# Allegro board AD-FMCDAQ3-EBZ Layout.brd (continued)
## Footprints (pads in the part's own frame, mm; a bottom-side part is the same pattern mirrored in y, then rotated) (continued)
QFN24_4X4_2PAD
  oval 0.305x0.889 smd: 1(-1.25,-2.05) 2(-0.75,-2.05) 3(-0.25,-2.05) 4(0.25,-2.05) 5(0.75,-2.05) 6(1.25,-2.05) 13(1.25,2.05) 14(0.75,2.05) 15(0.25,2.05) 16(-0.25,2.05) 17(-0.75,2.05) 18(-1.25,2.05)
  oval 0.889x0.305 smd: 7(2.05,-1.25) 8(2.05,-0.75) 9(2.05,-0.25) 10(2.05,0.25) 11(2.05,0.75) 12(2.05,1.25) 19(-2.05,1.25) 20(-2.05,0.75) 21(-2.05,0.25) 22(-2.05,-0.25) 23(-2.05,-0.75) 24(-2.05,-1.25)
  rect 1.397x2.692 smd: PAD1(-0.648,0)
  rect 0.94x2.692 smd: PAD2(0.876,0)
QFN56_8X8_PAD6_6X6_6
  oval 0.305x0.838 smd: 1(-3.25,-3.95) 2(-2.75,-3.95) 3(-2.25,-3.95) 4(-1.75,-3.95) 5(-1.25,-3.95) 6(-0.75,-3.95) 7(-0.25,-3.95) 8(0.25,-3.95) 9(0.75,-3.95) 10(1.25,-3.95) 11(1.75,-3.95) 12(2.25,-3.95) 13(2.75,-3.95) 14(3.25,-3.95) 29(3.25,3.95) 30(2.75,3.95) 31(2.25,3.95) 32(1.75,3.95) 33(1.25,3.95) 34(0.75,3.95) 35(0.25,3.95) 36(-0.25,3.95) 37(-0.75,3.95) 38(-1.25,3.95) 39(-1.75,3.95) 40(-2.25,3.95) 41(-2.75,3.95) 42(-3.25,3.95)
  oval 0.838x0.305 smd: 15(3.95,-3.25) 16(3.95,-2.75) 17(3.95,-2.25) 18(3.95,-1.75) 19(3.95,-1.25) 20(3.95,-0.75) 21(3.95,-0.25) 22(3.95,0.25) 23(3.95,0.75) 24(3.95,1.25) 25(3.95,1.75) 26(3.95,2.25) 27(3.95,2.75) 28(3.95,3.25) 43(-3.95,3.25) 44(-3.95,2.75) 45(-3.95,2.25) 46(-3.95,1.75) 47(-3.95,1.25) 48(-3.95,0.75) 49(-3.95,0.25) 50(-3.95,-0.25) 51(-3.95,-0.75) 52(-3.95,-1.25) 53(-3.95,-1.75) 54(-3.95,-2.25) 55(-3.95,-2.75) 56(-3.95,-3.25)
  rect 6.604x6.604 smd: PAD(0,0)
QFN64_9X9_PAD7_6X7_6
  oval 0.305x0.838 smd: 1(-3.75,-4.519) 2(-3.25,-4.519) 3(-2.75,-4.519) 4(-2.25,-4.519) 5(-1.75,-4.519) 6(-1.25,-4.519) 7(-0.75,-4.519) 8(-0.25,-4.519) 9(0.25,-4.519) 10(0.75,-4.519) 11(1.25,-4.519) 12(1.75,-4.519) 13(2.25,-4.519) 14(2.75,-4.519) 15(3.25,-4.519) 16(3.75,-4.519) 33(3.75,4.519) 34(3.25,4.519) 35(2.75,4.519) 36(2.25,4.519) 37(1.75,4.519) 38(1.25,4.519) 39(0.75,4.519) 40(0.25,4.519) 41(-0.25,4.519) 42(-0.75,4.519) 43(-1.25,4.519) 44(-1.75,4.519) 45(-2.25,4.519) 46(-2.75,4.519) 47(-3.25,4.519) 48(-3.75,4.519)
  oval 0.838x0.305 smd: 17(4.519,-3.75) 18(4.519,-3.25) 19(4.519,-2.75) 20(4.519,-2.25) 21(4.519,-1.75) 22(4.519,-1.25) 23(4.519,-0.75) 24(4.519,-0.25) 25(4.519,0.25) 26(4.519,0.75) 27(4.519,1.25) 28(4.519,1.75) 29(4.519,2.25) 30(4.519,2.75) 31(4.519,3.25) 32(4.519,3.75) 49(-4.519,3.75) 50(-4.519,3.25) 51(-4.519,2.75) 52(-4.519,2.25) 53(-4.519,1.75) 54(-4.519,1.25) 55(-4.519,0.75) 56(-4.519,0.25) 57(-4.519,-0.25) 58(-4.519,-0.75) 59(-4.519,-1.25) 60(-4.519,-1.75) 61(-4.519,-2.25) 62(-4.519,-2.75) 63(-4.519,-3.25) 64(-4.519,-3.75)
  rect 7.595x7.595 smd: PAD(0,0)
QFN72_10X10_PAD5_3X5_3
  oval 0.305x0.838 smd: 1(-4.25,-4.95) 2(-3.75,-4.95) 3(-3.25,-4.95) 4(-2.75,-4.95) 5(-2.25,-4.95) 6(-1.75,-4.95) 7(-1.25,-4.95) 8(-0.75,-4.95) 9(-0.25,-4.95) 10(0.25,-4.95) 11(0.75,-4.95) 12(1.25,-4.95) 13(1.75,-4.95) 14(2.25,-4.95) 15(2.75,-4.95) 16(3.25,-4.95) 17(3.75,-4.95) 18(4.25,-4.95) 37(4.25,4.95) 38(3.75,4.95) 39(3.25,4.95) 40(2.75,4.95) 41(2.25,4.95) 42(1.75,4.95) 43(1.25,4.95) 44(0.75,4.95) 45(0.25,4.95) 46(-0.25,4.95) 47(-0.75,4.95) 48(-1.25,4.95) 49(-1.75,4.95) 50(-2.25,4.95) 51(-2.75,4.95) 52(-3.25,4.95) 53(-3.75,4.95) 54(-4.25,4.95)
  oval 0.838x0.305 smd: 19(4.95,-4.25) 20(4.95,-3.75) 21(4.95,-3.25) 22(4.95,-2.75) 23(4.95,-2.25) 24(4.95,-1.75) 25(4.95,-1.25) 26(4.95,-0.75) 27(4.95,-0.25) 28(4.95,0.25) 29(4.95,0.75) 30(4.95,1.25) 31(4.95,1.75) 32(4.95,2.25) 33(4.95,2.75) 34(4.95,3.25) 35(4.95,3.75) 36(4.95,4.25) 55(-4.95,4.25) 56(-4.95,3.75) 57(-4.95,3.25) 58(-4.95,2.75) 59(-4.95,2.25) 60(-4.95,1.75) 61(-4.95,1.25) 62(-4.95,0.75) 63(-4.95,0.25) 64(-4.95,-0.25) 65(-4.95,-0.75) 66(-4.95,-1.25) 67(-4.95,-1.75) 68(-4.95,-2.25) 69(-4.95,-2.75) 70(-4.95,-3.25) 71(-4.95,-3.75) 72(-4.95,-4.25)
  rect 5.309x5.309 smd: PAD(0,0)
R0201
  rect 0.356x0.356 smd: 1(-0.318,0) 2(0.318,0)
R0402
  rect 0.889x0.813 smd: 1(-0.635,0) 2(0.635,0)
R0603
  rect 1.092x1.194 smd: 1(-0.851,0) 2(0.851,0)
R0805
  rect 1.295x1.397 smd: 1(-0.953,0) 2(0.953,0)
R1206
  rect 1.6x1.6 smd: 1(-1.397,0) 2(1.397,0)
SC70
  rect 0.406x0.508 smd: 1(-0.65,-0.95) 2(0,-0.95) 3(0.65,-0.95) 4(0.65,0.95) 5(0,0.95) 6(-0.65,0.95)
SO8
  rect 0.61x2.184 smd: 1(-1.905,-2.54) 2(-0.635,-2.54) 3(0.635,-2.54) 4(1.905,-2.54) 5(1.905,2.54) 6(0.635,2.54) 7(-0.635,2.54) 8(-1.905,2.54)
SO8NB-PAD3_1X2_41
  rect 0.635x1.524 smd: 1(-1.905,-2.667) 2(-0.635,-2.667) 3(0.635,-2.667) 4(1.905,-2.667) 5(1.905,2.667) 6(0.635,2.667) 7(-0.635,2.667) 8(-1.905,2.667)
  rect 3.099x2.413 smd: PAD(0,0)
TPSMC30
  round 0.762 smd: 1(0,0)
TSOT-5
  rect 0.508x1.524 smd: 1(-0.95,-1.17) 2(0,-1.17) 3(0.95,-1.17) 4(0.95,1.17) 5(-0.95,1.17)
unnamed#2
  round 1.016 smd: (0,0)
YSML276W197H63
  rect 1.956x1.778 smd: 1(-2.54,-1.83) 2(0,-1.83) 3(2.54,-1.83) 4(2.54,1.83) 5(0,1.83) 6(-2.54,1.83)

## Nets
AGND_SYSREF: C154.2(N2) R31.1 R68.1 U100.56 U100.60
GND: C2.2(N2) C4.1 C5.1 C5.3 C5.5 C5.7 C6.1 C7.1 C7.3 C7.5 C7.7 C9.1 C9.3 C9.5 C9.7 C10.1 C10.3 C10.5 C10.7 C12.1 C12.3 C12.5 C12.7 C13.2(N2) C18.2(N2) C22.1 C23.2(N2) C24.2(N2) C25.2(N2) C26.1 C27.2(N2) C28.2(N2) C29.1 C30.1 C31.N(N2) C32.1 C33.1 C34.2(N2) C35.1 C36.1 C37.1 C38.1 C39.2(N2) C43.1 C45.2(N2) C46.1 C47.1 C48.2(N2) C49.1 C50.1 C51.1 C52.1 C53.1 C54.1 C55.1 C56.1 C57.1 C58.1 C59.1 C60.1 C61.2(N2) C63.1 C64.1 C65.1 C66.1 C67.2(N2) C68.N(N2) C69.2(N2) C70.1 C71.1 C72.1 C73.1 C76.N(N2) C77.1 C78.1 C79.1 C80.1 C81.1 C82.1 C83.1 C89.2(N2) C90.1 C91.2(N2) C94.1 C96.N(N2) C97.1 C98.1 C100.2(N2) C101.1 C103.2(N2) C104.1 C105.1 C106.2(N2) C107.1 C109.1 C112.2(N2) C113.1 C114.1 C115.1 C116.2(N2) C117.1 C119.2(N2) C120.1 C121.1 C122.1 C123.2(N2) C125.2(N2) C126.2(N2) C127.1 C128.1 C129.2(N2) C130.2(N2) C131.2(N2) C133.2(N2) C134.2(N2) C135.2(N2) C136.2(N2) C137.2(N2) C138.2(N2) C139.2(N2) C140.2(N2) C141.2(N2) C142.2(N2) C143.2(N2) C144.2(N2) C145.2(N2) C146.2(N2) C147.2(N2) C148.2(N2) C149.2(N2) C150.2(N2) C151.2(N2) C152.2(N2) C153.2(N2) C155.2(N2) C156.1 C157.1 C158.1 C159.1 C160.1 C161.1 C163.2(N2) C164.2(N2) C165.2(N2) C166.2(N2) C167.N(N2) C169.1 C170.N(N2) C173.2(N2) C175.2(N2) C176.2(N2) C177.2(N2) C178.2(N2) C179.2(N2) C180.2(N2) C181.2(N2) C182.N(N2) C183.2(N2) C184.2(N2) C186.N(N2) C190.1 C191.1 C192.1 C195.2(N2) C197.2(N2) C199.1 C204.1 C205.1 C206.1 C207.2(N2) C208.2(N2) C209.2(N2) C210.2(N2) C211.2(N2) C212.2(N2) C216.1 C217.1 C218.2(N2) C219.1 C220.2(N2) C222.N(N2) C225.2(N2) C226.2(N2) C227.2(N2) C228.2(N2) C229.2(N2) C230.2(N2) C231.2(N2) C232.2(N2) C233.2(N2) C234.2(N2) C235.2(N2) C236.2(N2) C261.2(N2) C262.2(N2) C535.1 CC0.2(N2) CC02.1 CF1.1 CF2.1 CF3.1 CF4.1 CF5.1 CIN11.1 CIN12.1 CIN21.1 CIN22.1 CN4.1 CN4.3 CN4.5 CN4.7 CO1.1 CO2.1 CO3.1 CO4.1 CO5.1 CO6.1 CO7.1 CO8.1 CR1.C CSS1.1 CSS2.1 CVREG1.1 CVREG2.1 GND.1(N1) J1.2 J1.3 J1.4 J1.5(SH4) JP3.1 P501.A1 P501.A4 P501.A5 P501.A8 P501.A9 P501.A12 P501.A13 P501.A16 P501.A17 P501.A20 P501.A21 P501.A24 P501.A25 P501.A28 P501.A29 P501.A32 P501.A33 P501.A36 P501.A37 P501.A40 P501.B2 P501.B3 P501.B6 P501.B7 P501.B10 P501.B11 P501.B14 P501.B15 P501.B18 P501.B19 P501.B22 P501.B23 P501.B26 P501.B27 P501.B30 P501.B31 P501.B34 P501.B35 P501.B38 P501.B39 P501.C1 P501.C4 P501.C5 P501.C8 P501.C9 P501.C12 P501.C13 P501.C16 P501.C17 P501.C20 P501.C21 P501.C24 P501.C25 P501.C28 P501.C29 P501.C32 P501.C33 P501.C36 P501.C38 P501.C40 P501.D2 P501.D3 P501.D6 P501.D7 P501.D10 P501.D13 P501.D16 P501.D19 P501.D22 P501.D25 P501.D28 P501.D37 P501.D39 P501.E1 P501.E4 P501.E7 P501.E10 P501.E13 P501.E16 P501.E19 P501.E22 P501.E25 P501.E28 P501.E31 P501.E34 P501.E37 P501.E40 P501.F2 P501.F3 P501.F6 P501.F9 P501.F12 P501.F15 P501.F18 P501.F21 P501.F24 P501.F27 P501.F30 P501.F33 P501.F36 P501.F39 P501.G1 P501.G4 P501.G5 P501.G8 P501.G11 P501.G14 P501.G17 P501.G20 P501.G23 P501.G26 P501.G29 P501.G32 P501.G35 P501.G38 P501.G40 P501.H2 P501.H3 P501.H6 P501.H9 P501.H12 P501.H15 P501.H18 P501.H21 P501.H24 P501.H27 P501.H30 P501.H33 P501.H36 P501.H39 P501.J1 P501.J4 P501.J5 P501.J8 P501.J11 P501.J14 P501.J17 P501.J20 P501.J23 P501.J26 P501.J29 P501.J32 P501.J35 P501.J38 P501.J40 P501.K2 P501.K3 P501.K6 P501.K9 P501.K12 P501.K15 P501.K18 P501.K21 P501.K24 P501.K27 P501.K30 P501.K33 P501.K36 P501.K39 R1.2(N2) R7.1 R9.2(N2) R16.1 R17.1 R18.1 R19.1 R20.2(N2) R26.1 R31.2(N2) R33.2(N2) R36.1 R38.2(N2) R39.1 R42.1 R43.1 R44.1 R48.2(N2) R50.1 R52.1 R57.2(N2) R58.2(N2) R60.1 R62.1 R64.1 R65.1 R67.1 R68.2(N2) R69.1 R70.1 R73.1 R79.2(N2) R80.1 R81.1 R85.2(N2) R92.2(N2) R93.1 R100.1 R116.1 R117.1 R120.1 R121.2(N2) R138.2(N2) RC1.1 RC12.1 RF2.1 RT1.2(N2) RT22.1 RX_A.2 RX_A.3 RX_A.4 RX_A.5(SH4) RX_B.2 RX_B.3 RX_B.4 RX_B.5(SH4) T3.3 T4.1 T100.1 T100.4 T101.4 T102.1 T102.4 T103.5(N4) TP1.1(N1) TX_A.2 TX_A.3 TX_A.4 TX_A.5(SH4) TX_B.2 TX_B.3 TX_B.4 TX_B.5(SH4) U1.PAD U2.3 U2.4 U3.4 U3.8 U3.9 U3.10 U3.11 U3.12 U3.13 U3.PAD1 U4.2 U5.6 U5.PAD U6.4 U6.8 U6.9 U6.10 U6.11 U6.12 U6.13 U6.PAD1 U7.9 U7.13 U7.PAD U8.4 U8.PAD U9.2 U10.3 U10.6 U10.PAD U11.3 U11.6 U11.PAD U12.11 U12.12 U12.13 U13.11 U13.12 U13.13 U14.2 U14.4 U15.4 U16.2 U17.6 U17.PAD U18.6 U18.9 U18.PAD U19.6 U19.PAD U22.2 U100.16 U100.18 U100.31 U100.33 U100.PAD Y1.3
P1V7: C167.P C186.P CO5.2(N2) CO6.2(N2) CO7.2(N2) CO8.2(N2) L12.2(N2) R40.2(N2) RFB2.2(N2) TP3.1(N1) U17.1 U17.2 U17.3 U17.4 U17.15 U17.16 U19.1 U19.2 U19.3 U19.4 U19.15 U19.16
P2V5_EN: U4.4(Y2) U5.4
P3V3_CLK_OUT: C24.1 C30.2(N2) C32.2(N2) C59.2(N2) C63.2(N2) C65.2(N2) C66.2(N2) C70.2(N2) C72.2(N2) C77.2(N2) C78.2(N2) C79.2(N2) C80.2(N2) C82.2(N2) C83.2(N2) E11.2(N2) U7.27 U7.30 U7.33 U7.36 U7.39 U7.42 U7.45 U7.48 U7.51 U7.54 U7.60 U7.63 U7.66 U7.69
P3V3_CLK_PLL: C23.1 C60.2(N2) C64.2(N2) C71.2(N2) C73.2(N2) C81.2(N2) E8.2(N2) U7.1 U7.10 U7.16 U7.20 U7.72(VDD_5)
P3V6: C18.1 C34.1 C48.1 C106.1 C112.1 C149.1 C152.1 C163.1 C166.1 C262.1 CO1.2(N2) CO2.2(N2) CO3.2(N2) CO4.2(N2) L11.2(N2) R33.1 R63.2(N2) RFB1.2(N2) TP2.1(N1) U4.3 U8.7 U8.8 U10.5 U10.8 U11.5 U11.8 U16.1 U16.3 U22.1 U22.3
VINA1_N: C187.1 T100.5(N4) T101.1
VINA1_P: C108.1 T100.3 T101.3
VINA_N: C196.1 R109.2(N2) U100.5
VINA_P: C196.2(N2) R108.2(N2) U100.6
VINB1_N: C118.1 T102.3 T103.3
VINB1_P: C188.1 T102.5(N4) T103.1
VINB_N: C198.2(N2) R126.2(N2) U100.44
VINB_P: C198.1 R127.2(N2) U100.43
3P3_SUP: C25.1 C28.1 C68.P C76.P C91.1 C233.1 C234.1 C261.1 R27.2(N2) U9.6(VCCB) U12.23 U12.24(VCCB2) U13.23 U13.24(VCCB2) U14.1(VCC) U15.1(VCC) U22.5(VOUT)
3P3_XO: C119.1 C126.1 C184.1 C535.2(N2) R6.1 U16.5(VOUT) Y1.6(VDD)
ADC_1P0: C100.1 U100.12(V_1P0)
ADC_1P2_AVDD: C135.1 C136.1 C137.1 C138.1 C139.1 C144.1 C145.1 C146.1 C147.1 C225.1 E1.2(N2) U100.1 U100.2 U100.47 U100.48 U100.49 U100.52 U100.55 U100.61 U100.64
ADC_1P2_AVDD_SR: C154.1 C226.1 E2.2(N2) U100.57
ADC_1P2_DRVDD: C155.1 C208.1 C209.1 C210.1 C211.1 C212.1 C232.1 E9.2(N2) U100.19 U100.30
ADC_1P2_DVDD: C153.1 C207.1 C227.1 E3.2(N2) U100.15 U100.34
ADC_2P5_AVDD: C96.P C123.1 C125.1 C129.1 C130.1 C131.1 C133.1 C134.1 C173.1 C175.1 C176.1 C177.1 C179.1 C195.1 E17.2(N2) R61.2(N2) U100.3 U100.8 U100.9 U100.10 U100.11 U100.39 U100.40 U100.41 U100.46 U100.50 U100.51 U100.62 U100.63
ADC_3P3_AVDD: C140.1 C141.1 C142.1 C143.1 C181.1 E20.2(N2) U100.4 U100.7 U100.42 U100.45
ADC_3P3_SPIVDD: C150.1 C151.1 C220.1 E21.2(N2) U100.13 U100.38
ADC_CLK1_N: C40.1 U7.26
ADC_CLK1_P: C41.1 U7.25
ADC_CLK_FMC1_N: C168.1 U7.53
ADC_CLK_FMC1_P: C162.1 U7.52
ADC_CLK_FMC_N: C174.2(N2) P501.B21
ADC_CLK_FMC_P: C171.2(N2) P501.B20
ADC_CLK_N: C40.2(N2) R56.1 U100.54
ADC_CLK_P: C41.2(N2) R56.2(N2) U100.53
ADC_FDA: R77.2(N2) U100.17
ADC_FDB: R78.2(N2) U100.32
ADC_PD: R95.2(N2) U100.14
ADC_REFCLK_N: C193.2(N2) P501.G7
ADC_REFCLK_P: C194.2(N2) P501.G6
ADC_SERDOUT0_N: C20.2(N2) U100.22
ADC_SERDOUT0_P: C8.2(N2) U100.23
ADC_SERDOUT1_N: C85.2(N2) U100.24
ADC_SERDOUT1_P: C84.2(N2) U100.25
ADC_SERDOUT2_N: C87.2(N2) U100.26
ADC_SERDOUT2_P: C86.2(N2) U100.27
ADC_SERDOUT3_N: C92.2(N2) U100.28
ADC_SERDOUT3_P: C88.2(N2) U100.29
ADC_SPI_CSB: ADC_CSB.1(N1) R97.2(N2) U100.37
ADC_SYNC_N: P501.D9 R72.1 U100.20
ADC_SYNC_P: P501.D8 R72.2(N2) U100.21
ADC_SYSREF1_N: C14.1 U7.50
ADC_SYSREF1_P: C19.1 U7.49
ADC_SYSREF_N: C172.2(N2) R55.1 U100.59
ADC_SYSREF_P: C15.2(N2) R55.2(N2) U100.58
CLKD_SPI_CSB: CLKD_CSB.1(N1) R94.2(N2) U7.21
CLKD_STATUS0: R82.2(N2) U7.56
CLKD_STATUS1: R76.2(N2) U7.55
CLKD_SYSREF_ADC1_N: C21.1 U7.47
CLKD_SYSREF_ADC1_P: C17.1 U7.46
CLKD_SYSREF_ADC_N: C11.2(N2) P501.G10
CLKD_SYSREF_ADC_P: C16.2(N2) P501.G9
CLKD_SYSREF_DAC1_N: C11.1 U7.44
CLKD_SYSREF_DAC1_P: C16.1 U7.43
CLKD_SYSREF_DAC_N: C21.2(N2) P501.H11
CLKD_SYSREF_DAC_P: C17.2(N2) P501.H10
DAC_1P2_CVDD12: C9.2 C9.4 C9.6 C9.8(N8) C35.2(N2) C38.2(N2) C90.2(N2) C97.2(N2) C104.2(N2) C113.2(N2) C120.2(N2) C127.2(N2) C231.1 E7.2(N2) U1.2 U1.47 U1.50 U1.56
DAC_1P2_DVDD12: C5.2 C5.4 C5.6 C5.8(N8) C98.2(N2) C114.2(N2) C121.2(N2) C128.2(N2) C229.1 E5.2(N2) U1.11 U1.35 U1.36
DAC_1P2_PVDD12: C7.2 C7.4 C7.6 C7.8(N8) C29.2(N2) C36.2(N2) C49.2(N2) C53.2(N2) C228.1 E4.2(N2) U1.5 U1.21
DAC_1P2_SVDD12: C6.2(N2) C10.2 C10.4 C10.6 C10.8(N8) C12.2 C12.4 C12.6 C12.8(N8) C22.2(N2) C26.2(N2) C33.2(N2) C37.2(N2) C43.2(N2) C47.2(N2) C50.2(N2) C52.2(N2) C54.2(N2) C55.2(N2) C56.2(N2) C94.2(N2) C101.2(N2) C109.2(N2) C117.2(N2) C122.2(N2) C204.2(N2) C205.2(N2) C206.2(N2) C230.1 E6.2(N2) U1.12 U1.13 U1.14 U1.17 U1.20 U1.23 U1.26 U1.29 U1.30(VTT2) U1.31
DAC_3P3_AVDD33: C42.1 C44.1 C46.2(N2) C51.2(N2) C156.2(N2) C157.2(N2) C158.2(N2) C159.2(N2) C160.2(N2) C161.2(N2) C164.1 CN4.2 CN4.4 CN4.6 CN4.8(N8) E10.2(N2) R15.1 R22.2(N2) R23.1 R25.2(N2) U1.43 U1.46 U1.51 U1.54
DAC_3P3_IOVDD33: C57.2(N2) C58.2(N2) C180.1 C191.2(N2) C192.2(N2) E12.2(N2) R122.2(N2) U1.32 U1.42
DAC_CLK1_N: C1.1 U7.62
DAC_CLK1_P: C3.1 U7.61
DAC_CLK_FMC1_N: C174.1 U7.38
DAC_CLK_FMC1_P: C171.1 U7.37
DAC_CLK_FMC_N: C168.2(N2) P501.D5
DAC_CLK_FMC_P: C162.2(N2) P501.D4
DAC_CLK_N: C1.2(N2) R14.2(N2) U1.49
DAC_CLK_P: C3.2(N2) R14.1 U1.48
DAC_IRQ: R84.2(N2) U1.10
DAC_REFCLK_N: C185.2(N2) P501.D21
DAC_REFCLK_P: C189.2(N2) P501.D20
DAC_SERDIN0_N: C95.2(N2) U1.16
DAC_SERDIN0_P: C93.2(N2) U1.15
DAC_SERDIN1_N: C102.2(N2) U1.19
DAC_SERDIN1_P: C99.2(N2) U1.18
DAC_SERDIN2_N: C111.2(N2) U1.24
DAC_SERDIN2_P: C110.2(N2) U1.25
DAC_SERDIN3_N: C132.2(N2) U1.27
DAC_SERDIN3_P: C124.2(N2) U1.28
DAC_SPI_CSB: R98.2(N2) U1.41
DAC_SYNC_N: P501.H8 U1.33
DAC_SYNC_P: P501.H7 U1.34
DAC_SYSREF1_N: C172.1 U7.41
DAC_SYSREF1_P: C15.1 U7.40
DAC_SYSREF_N: C14.2(N2) R13.2(N2) U1.7
DAC_SYSREF_P: C19.2(N2) R13.1 U1.6
DAC_TXEN: R96.2(N2) U1.8
DLOGIC_0: P501.A14 P501.A18 P501.B4 P501.B8 P501.B12 P501.B16 P501.H4 P501.J2 P501.K4 U14.7
DLOGIC_1: P501.A15 P501.A19 P501.B5 P501.B9 P501.B13 P501.B17 P501.H5 P501.J3 P501.K5 U14.8
EXT_TRIG_N: P501.H14 R35.2(N2) U15.8
EXT_TRIG_P: P501.H13 R35.1 U15.7
FMC_3P3V: C31.P C69.1 P501.C39 P501.D36 P501.D38 P501.D40 R32.1 R59.2(N2) U4.5 U5.1 U5.2 U5.3 U5.15 U5.16 UNK3P3V.1
FMC_3P3VAUX: C67.1 C217.2(N2) C218.1 P501.D32 R12.2(N2) R28.1 R29.1 R30.1 U2.8 U18.10 U18.16 U18.17
FMC_12P0V: C237.2(N2) LIN1.1 LIN2.1 P501.C35 P501.C37 R66.2(N2) UNK12P0V.1
FMC_ADC_FDA: P501.H16 R45.1
FMC_ADC_FDB: P501.H17 R71.1
FMC_ADC_PD: P501.C10 R87.1
FMC_ADC_SPI_CSB: P501.D15 R89.1
FMC_CLK_DIR: P501.B1 R19.2(N2)
FMC_CLKD_SPI_CSB: P501.D11 R86.1
FMC_CLKD_STATUS0: P501.G12 R74.1
FMC_CLKD_STATUS1: P501.G13 R41.1
FMC_DAC_IRQ: P501.G15 R75.1
FMC_DAC_SPI_CSB: P501.C14 R90.1
FMC_DAC_TXEN: P501.G16 R88.1
FMC_GA0: P501.C34 R11.1 U18.11
FMC_GA1: P501.D35 R10.1 U18.13
FMC_PG_C2M: P501.D1 U3.20 U6.20
FMC_SCL: P501.C30 R28.2(N2) U2.6 U18.15
FMC_SDA: P501.C31 R30.2(N2) U2.5 U18.14
FMC_SERDIN0_N: C95.1 P501.A31
FMC_SERDIN0_P: C93.1 P501.A30
FMC_SERDIN1_N: C102.1 P501.A27
FMC_SERDIN1_P: C99.1 P501.A26
FMC_SERDIN2_N: C111.1 P501.A23
FMC_SERDIN2_P: C110.1 P501.A22
FMC_SERDIN3_N: C132.1 P501.C3
FMC_SERDIN3_P: C124.1 P501.C2
FMC_SERDOUT0_N: C20.1 P501.A11
FMC_SERDOUT0_P: C8.1 P501.A10
FMC_SERDOUT1_N: C85.1 P501.C7
FMC_SERDOUT1_P: C84.1 P501.C6
FMC_SERDOUT2_N: C87.1 P501.A7
FMC_SERDOUT2_P: C86.1 P501.A6
FMC_SERDOUT3_N: C92.1 P501.A3
FMC_SERDOUT3_P: C88.1 P501.A2
FMC_SPI_SCLK: P501.D12 R91.1
FMC_SPI_SDIO: P501.D14 R115.1
FMC_SPI_SDIO_CTRL: P501.C11 U9.5
FMC_SYSREF_N: P501.D18 R112.1
FMC_SYSREF_N_A: R112.2(N2) R114.2(N2) U7.71
FMC_SYSREF_P: P501.D17 R113.1
FMC_SYSREF_P_A: R113.2(N2) R114.1 U7.70
FMC_VADJ: C89.1 C235.1 C236.1 P501.E39 P501.F40 P501.G39 P501.H40 R8.1 R24.2(N2) R119.2(N2) U9.1 U12.1 U13.1 VADJ.1(N1)
LDO_VCO_2P5: C62.1 C103.1 U7.15
LF_EXT_CAP: C2.1 R2.1 U7.7
LF_PLL2: R83.2(N2) U7.14
OUT0_N: R22.1 T2.1 U1.52
OUT0_P: R15.2(N2) T2.3 U1.53
OUT1_N: R23.2(N2) T1.3 U1.45
OUT1_P: R25.1 T1.1 U1.44
PWRGD: R32.2(N2) U3.21 U4.1 U5.5 U6.21 U10.7 U11.7 U17.5 U19.5
SPI_SCLK: R99.2(N2) R101.1 R104.1 R106.2(N2) SCLK.1(N1)
SPI_SDIO: R4.1 R105.1 R107.2(N2) R118.2(N2) SDIO.1(N1)
SW1: CBST1.2(N2) L1.1 R3.1 U6.5 U6.6 U6.7 U6.14 U6.PAD2
UNNAMED_2_AD9152_I234_I120: R17.2(N2) U1.55
UNNAMED_2_AD9152_I234_LDOBYP1: C199.2(N2) U1.1
UNNAMED_2_AD9152_I234_LDOBYP2: C39.1 U1.22
UNNAMED_2_AD9152_I234_PAPOUT0: R20.1 U1.37
UNNAMED_2_AD9152_I234_REFCLK: R16.2(N2) U1.3
UNNAMED_2_AD9152_I234_REFCLK_1: R18.2(N2) U1.4
UNNAMED_2_AD9152_I234_RESETB: R122.1 U1.9
UNNAMED_2_AD9152_I234_SPICLK: R106.1 U1.40
UNNAMED_2_AD9152_I234_SPISDIO: R107.1 U1.39
UNNAMED_2_CAP_I167_N2: C44.2(N2) T4.5
UNNAMED_2_CAP_I184_N2: C42.2(N2) T3.5
UNNAMED_2_CNBNC5P_I224_CNTR: T4.3 TX_B.1
UNNAMED_2_CNBNC5P_I229_CNTR: T3.1 TX_A.1
UNNAMED_2_XFMRETC1_I243_N3: T2.4 T3.4(SECP)
UNNAMED_2_XFMRETC1_I243_N4: T2.5(N4) T3.6
UNNAMED_2_XFMRETC1_I246_N3: T1.4 T4.4(SECP)
UNNAMED_2_XFMRETC1_I246_N4: T1.5(N4) T4.6
UNNAMED_4_AD9528_I220_OUT3: C189.1 U7.58
UNNAMED_4_AD9528_I220_OUT3N: C185.1 U7.59
UNNAMED_4_AD9528_I220_OUT10: C194.1 U7.34
UNNAMED_4_AD9528_I220_OUT10N: C193.1 U7.35
UNNAMED_4_AD9528_I220_SCLK: R101.2(N2) U7.22
UNNAMED_4_AD9528_I220_SDIO: R4.2(N2) U7.23
UNNAMED_4_CAP_I87_N1: C75.1 R58.1 Y1.5
UNNAMED_4_CAP_I87_N2: C75.2(N2) R5.2(N2) U7.12
UNNAMED_4_CAP_I90_N1: C74.1 R48.1 Y1.4
UNNAMED_4_CAP_I90_N2: C74.2(N2) R5.1 U7.11
UNNAMED_4_CAP_I173_N1: C61.1 R2.2(N2)
UNNAMED_4_CAP_I217_N2: C62.2(N2) R83.1
UNNAMED_4_RES_I223_N2: R1.1 R6.2(N2) Y1.1
UNNAMED_5_AD9680_I130_SCLK: R104.2(N2) U100.36
UNNAMED_5_AD9680_I130_SDIO: R105.2(N2) U100.35
UNNAMED_5_CAP_I52_N2: C108.2(N2) R103.1
UNNAMED_5_CAP_I53_N2: C187.2(N2) R102.1
UNNAMED_5_CAP_I54_N2: C107.2(N2) R110.2(N2) R111.1
UNNAMED_5_CAP_I67_N2: C190.2(N2) R128.2(N2) R129.1
UNNAMED_5_CAP_I68_N2: C188.2(N2) R54.1
UNNAMED_5_CAP_I69_N2: C118.2(N2) R53.1
UNNAMED_5_CAP_I181_N2: C105.2(N2) R103.2(N2) R108.1 R110.1
UNNAMED_5_CAP_I182_N1: C197.1 R102.2(N2) R109.1 R111.2(N2)
UNNAMED_5_CAP_I183_N2: C115.2(N2) R53.2(N2) R126.1 R128.1
UNNAMED_5_CAP_I184_N1: C116.1 R54.2(N2) R127.1 R129.2(N2)
UNNAMED_5_CNBNC5P_I49_CNTR: R121.1 RX_A.1 T101.5(N4)
UNNAMED_5_CNBNC5P_I70_CNTR: R138.1 RX_B.1 T103.4
UNNAMED_6_CN400PAKV2_I20_TDI: P501.D30 P501.D31
UNNAMED_7_AD7291_I66_DCAP: C216.2(N2) U18.8
UNNAMED_7_AD7291_I66_VIN5: R66.1 R67.2(N2) U18.3
UNNAMED_7_AD7291_I66_VIN6: R24.1 R26.2(N2) U18.4
UNNAMED_7_AD7291_I66_VIN7: R27.1 R36.2(N2) U18.5
UNNAMED_7_AD7291_I66_VREF: C219.2(N2) U18.7(VREF)
UNNAMED_7_ADN4661_I56_DIN: J1.1 R9.1 U15.2
UNNAMED_7_DIOLED_I43_P: CR1.A(P) R34.2(N2)
UNNAMED_7_ICFXL4245_I164_A0: R74.2(N2) U13.3
UNNAMED_7_ICFXL4245_I164_A1: R41.2(N2) U13.4
UNNAMED_7_ICFXL4245_I164_A2: R75.2(N2) U13.5
UNNAMED_7_ICFXL4245_I164_A3: R45.2(N2) U13.6
UNNAMED_7_ICFXL4245_I164_A4: R71.2(N2) U13.7
UNNAMED_7_ICFXL4245_I164_A5: R65.2(N2) U13.8
UNNAMED_7_ICFXL4245_I164_A6: R73.2(N2) U13.9
UNNAMED_7_ICFXL4245_I164_A7: R70.2(N2) U13.10
UNNAMED_7_ICFXL4245_I164_B0: R82.1 U13.21
UNNAMED_7_ICFXL4245_I164_B1: R76.1 U13.20
UNNAMED_7_ICFXL4245_I164_B2: R84.1 U13.19
UNNAMED_7_ICFXL4245_I164_B3: R77.1 U13.18
UNNAMED_7_ICFXL4245_I164_B4: R78.1 U13.17
UNNAMED_7_ICFXL4245_I164_B5: R116.2(N2) U13.16
UNNAMED_7_ICFXL4245_I164_B6: R81.2(N2) U13.15
UNNAMED_7_ICFXL4245_I164_B7: R117.2(N2) U13.14
UNNAMED_7_ICFXL4245_I164_OEN: R80.2(N2) U13.22
UNNAMED_7_ICFXL4245_I164_TRN: R79.1 U13.2
UNNAMED_7_ICFXL4245_I213_A0: R91.2(N2) U12.3
UNNAMED_7_ICFXL4245_I213_A1: R85.1 U12.4
UNNAMED_7_ICFXL4245_I213_A2: R92.1 U12.5
UNNAMED_7_ICFXL4245_I213_A3: R86.2(N2) U12.6
UNNAMED_7_ICFXL4245_I213_A4: R89.2(N2) U12.7
UNNAMED_7_ICFXL4245_I213_A5: R87.2(N2) U12.8
UNNAMED_7_ICFXL4245_I213_A6: R90.2(N2) U12.9
UNNAMED_7_ICFXL4245_I213_A7: R88.2(N2) U12.10
UNNAMED_7_ICFXL4245_I213_B0: R99.1 U12.21
UNNAMED_7_ICFXL4245_I213_B1: R100.2(N2) U12.20
UNNAMED_7_ICFXL4245_I213_B2: R93.2(N2) U12.19
UNNAMED_7_ICFXL4245_I213_B3: R94.1 U12.18
UNNAMED_7_ICFXL4245_I213_B4: R97.1 U12.17
UNNAMED_7_ICFXL4245_I213_B5: R95.1 U12.16
UNNAMED_7_ICFXL4245_I213_B6: R98.1 U12.15
UNNAMED_7_ICFXL4245_I213_B7: R96.1 U12.14
UNNAMED_7_ICFXL4245_I213_OEN: R120.2(N2) U12.22
UNNAMED_7_ICFXL4245_I213_TRN: R119.1 U12.2
UNNAMED_7_ICFXLH1T45_I232_A: R115.2(N2) U9.3
UNNAMED_7_ICFXLH1T45_I232_B: R118.1 U9.4
UNNAMED_7_ICM24CXX_I21_E0: R10.2(N2) U2.1
UNNAMED_7_ICM24CXX_I21_E1: R11.2(N2) U2.2
UNNAMED_7_ICM24CXX_I21_WCN: JP3.2(N2) R29.2(N2) U2.7(WC_N)
UNNAMED_7_NC7WZ17P6X_I12_Y1: R34.1 U4.6
UNNAMED_7_RES_I67_N1: R12.1 R39.2(N2) U18.20
UNNAMED_7_RES_I85_N1: R59.1 R60.2(N2) U18.19
UNNAMED_7_RES_I87_N2: R63.1 R64.2(N2) U18.18
UNNAMED_7_RES_I91_N1: R61.1 R62.2(N2) U18.2
UNNAMED_7_RES_I93_N1: R40.1 R42.2(N2) U18.1
UNNAMED_8_ADM7154_I184_BYP: C165.1 U8.3
UNNAMED_8_ADM7154_I184_REF: C183.1 U8.5 U8.6
UNNAMED_8_ADM7154_I184_VREG: C178.1 U8.1(VREG)
UNNAMED_8_ADP238X_I102_BST: CBST1.1 U6.15
UNNAMED_8_ADP238X_I102_COMP: CC0.1 CC1.1 U6.1
UNNAMED_8_ADP238X_I102_RT: RT1.1 U6.22
UNNAMED_8_ADP238X_I102_SS: CSS1.2(N2) U6.24
UNNAMED_8_ADP238X_I102_VREG: CVREG1.2(N2) U6.3(VREG)
UNNAMED_8_ADP1755_I190_ADJ: R37.2(N2) R38.1 U5.9
UNNAMED_8_ADP1755_I190_SS: C148.1 U5.7
UNNAMED_8_ADP1755_I190_VOUT1: C182.P E17.1 R37.1 U5.10 U5.11 U5.12 U5.13 U5.14(VOUT5)
UNNAMED_8_ADP7104_I66_SENSE: R44.2(N2) R47.1 U11.2
UNNAMED_8_ADP7104_I66_VOUT: C45.1 E20.1 E21.1 R47.2(N2) U11.1(VOUT)
UNNAMED_8_ADP7104_I68_SENSE: R43.2(N2) R46.1 U10.2
UNNAMED_8_ADP7104_I68_VOUT: C13.1 E10.1 E12.1 R46.2(N2) U10.1(VOUT)
UNNAMED_8_CAP_I10_N2: CC1.2(N2) RC1.2(N2)
UNNAMED_8_CAP_I92_N1: C27.1 E8.1 E11.1 U8.2
UNNAMED_8_CAP_I104_N1: CF1.2(N2) CF2.2(N2) CF3.2(N2) CFB1.1 L1.2(N2) L11.1
UNNAMED_8_CAP_I104_N2: CFB1.2(N2) RF1.2(N2) RFB1.1
UNNAMED_8_CAP_I171_N2: CIN11.2(N2) CIN21.2(N2) LIN1.2(N2) U6.16 U6.17 U6.18 U6.19
UNNAMED_8_CAP_I177_N1: C237.1 R69.2(N2)
UNNAMED_8_RES_I185_N2: RF1.1 RF2.2(N2) U6.2
UNNAMED_9_ADP238X_I75_BST: CBST2.1 U3.15
UNNAMED_9_ADP238X_I75_COMP: CC02.2(N2) CC12.2(N2) U3.1
UNNAMED_9_ADP238X_I75_RT: RT22.2(N2) U3.22
UNNAMED_9_ADP238X_I75_SS: CSS2.2(N2) U3.24
UNNAMED_9_ADP238X_I75_SW1: CBST2.2(N2) L10.1 U3.5 U3.6 U3.7 U3.14 U3.PAD2
UNNAMED_9_ADP238X_I75_VREG: CVREG2.2(N2) U3.3(VREG)
UNNAMED_9_ADP1741_I185_ADJ: R49.1 R50.2(N2) U17.9
UNNAMED_9_ADP1741_I185_SS: C169.2(N2) U17.7
UNNAMED_9_ADP1741_I185_VOUT: C170.P E1.1 E2.1 E3.1 E9.1 R49.2(N2) U17.10 U17.11 U17.12 U17.13 U17.14(VOUT4)
UNNAMED_9_ADP1741_I188_ADJ: R51.1 R52.2(N2) U19.9
UNNAMED_9_ADP1741_I188_SS: C4.2(N2) U19.7
UNNAMED_9_ADP1741_I188_VOUT: C222.P E4.1 E5.1 E6.1 E7.1 R51.2(N2) U19.10 U19.11 U19.12 U19.13 U19.14(VOUT4)
UNNAMED_9_CAP_I146_N1: CC12.1 RC12.2(N2)
UNNAMED_9_CAP_I148_N1: CFB2.1 R21.2(N2) RFB2.1
UNNAMED_9_CAP_I148_N2: CF4.2(N2) CF5.2(N2) CFB2.2(N2) L10.2(N2) L12.1
UNNAMED_9_CAP_I180_N2: CIN12.2(N2) CIN22.2(N2) LIN2.2(N2) U3.16 U3.17 U3.18 U3.19
UNNAMED_9_RES_I163_N1: R3.2(N2) R57.1 U3.23
UNNAMED_9_RES_I176_N1: R7.2(N2) R21.1 U3.2
VIO_B_M2C: P501.J39 P501.K40 R8.2(N2)

Pads without a net: P501 A34 A35 A38 A39 B24 B25 B28 B29 B32 B33 B36 B37 B40 C15 C18 C19 C22 C23 C26 C27 D23 D24 D26 D27 D29 D33 D34 E2 E3 E5 E6 E8 E9 E11 E12 E14 E15 E17 E18 E20 E21 E23 E24 E26 E27 E29 E30 E32 E33 E35 E36 E38 F1 F4 F5 F7 F8 F10 F11 F13 F14 F16 F17 F19 F20 F22 F23 F25 F26 F28 F29 F31 F32 F34 F35 F37 F38 G2 G3 G18 G19 G21 G22 G24 G25 G27 G28 G30 G31 G33 G34 G36 G37 H1 H19 H20 H22 H23 H25 H26 H28 H29 H31 H32 H34 H35 H37 H38 J6 J7 J9 J10 J12 J13 J15 J16 J18 J19 J21 J22 J24 J25 J27 J28 J30 J31 J33 J34 J36 J37 K1 K7 K8 K10 K11 K13 K14 K16 K17 K19 K20 K22 K23 K25 K26 K28 K29 K31 K32 K34 K35 K37 K38; T1 2; T2 2; T3 2; T4 2; T100 2; T101 2; T102 2; T103 2; U1 38; U5 8; U6 23; U7 2 3 4 5 6 8 17 18 19 24 28 29 31 32 57 64 65 67 68; U10 4; U11 4; U12 PAD; U13 PAD; U14 3 5 6; U15 3 5 6; U16 4; U17 8; U18 12; U19 8; U22 4; Y1 2

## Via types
v1: diameter 0.406, hole 0.203, TOP to L2_AGND, 1099 vias
v2: diameter 0.508, hole 0.254, L2_AGND to L9_AGND, 785 vias
v3: diameter 0.406, hole 0.203, L9_AGND to BOTTOM, 847 vias
v4: diameter 0.508, hole 0.254, TOP to BOTTOM, 807 vias

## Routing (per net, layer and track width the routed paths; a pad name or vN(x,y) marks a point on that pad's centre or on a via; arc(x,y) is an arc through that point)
AGND_SYSREF: length 13.4
  BOTTOM w0.254: U100.60 20.11,22.28 20.07,22.23 17.87,22.23 17.29,22.82 ; 18.18,20.47 18.49,20.78 19,20.78 C154.2 19,20.4 19.13,20.28 U100.56
  BOTTOM w0.305: 18.18,20.47 15.89,20.47 R31.1 R68.1 15.32,22.12 16.02,22.82 17.29,22.82
GND: length 916.7
  TOP w0.254: U8.4 14.17,25.6 U8.PAD ; C5.1 v1(36.15,55.71) ; CN4.7 v1(23.58,53.43) ; U13.13 77.56,28.78 ; 26.63,35.26 U7.9 ; U13.11 77.41,27.78 v1(77.55,27.64) ; C7.3 v1(30.18,56.22) ; U12.13 77.56,43.13 ; C12.3 v1(37.55,42.63) ; C9.3 v1(27.51,53.93) ; U7.13 27.41,33.26 v1(27.64,33.49) ; CN4.3 v1(21.29,52.92) ; U12.12 77.56,42.63 ; C12.1 v1(37.55,43.65) ; C10.3 v1(39.83,53.93) ; C7.1 v1(30.18,57.24) ; C9.5 v1(25.23,54.44) ; C5.3 v1(36.15,56.73) ; C10.1 v1(39.83,52.92) ; U13.12 77.56,28.28 ; CN4.5 v1(23.58,52.41) ; C10.5 v1(37.55,54.44) ; C9.7 v1(25.23,53.43) ; C10.7 v1(37.55,53.43) ; v1(77.55,42) 77.41,42.13 U12.11 ; U9.2 v1(74.63,18.12) ; C7.5 v1(32.47,55.71) ; CN4.1 v1(21.29,53.93)
  TOP w0.305: v1(35.16,54.12) C37.1 35.01,54.67 ; 6.72,33.8 C184.2 ; C184.2 6.72,35.71 ; C184.2 5.82,34.76 ; U15.4 45.34,20.53 ; U15.4 43.9,19.87 ; U15.4 42.45,20.53 ; 24.64,49.55 R17.1 25.41,50.35 ; v1(68.11,24.97) v1(66.84,26.24) P501.C13 ; P501.K2 P501.J1 P501.H2 P501.G1 P501.F2 v1(63.03,9.73) P501.D2 ; C12.5 40,42.12 ; C12.5 39.32,41.61 ; C12.5 v1(38.84,42.12) ; 61.77,16.08 v1(61.8,16.08) ; 61.77,16.08 P501.E7 v1(64.3,16.08) ; 61.77,16.08 P501.F6 v1(60.49,14.81) P501.H6 ; v1(71.07,63.33) 71.84,63.33 ; v1(71.07,63.33) 71.07,64.13 ; v1(71.07,63.33) 70.31,63.33 ; v1(64.3,17.35) P501.C8 P501.B7 P501.A8 ; 13.1,43 C106.2 ; C106.2 14.1,44.15 ; C106.2 13.1,45.31 ; v1(71.58,66.89) 72.34,66.89 ; v1(71.58,66.89) 71.58,67.69 ; v1(71.58,66.89) 70.82,66.89 ; 71.07,23.41 v1(71.07,24.22) 71.84,24.22 ; P501.J23 P501.K24 ; C143.2 v1(23.32,14.82) ; P501.G20 P501.F21 61.77,35.13 ; v1(65.57,14.81) P501.B6 66.85,16.08 v1(66.88,16.08) 66.88,16.04 P501.A5 ; C43.1 v1(35.77,41.36) ; 45.55,12.75 C25.2 ; C25.2 46.31,13.55 ; C25.2 44.78,13.55 ; C205.1 v1(38.33,46.31) C26.1 ; C205.1 v1(38.32,47.1) C47.1 38.85,47.46 ; C205.1 38.85,46.69 ; 25.93,46.44 C157.1 v1(25.66,45.91) 25.33,45.91 ; v1(34.37,57.82) C5.5 ; P501.E40 P501.F39 P501.G38 ; 27.4,35.26 U7.9 26.12,35.26 25.67,35.71 C71.1 v1(24.91,35.71) 24.15,35.71 v1(23.83,36.03) ; v1(63.07,40.21) 63.04,40.21 P501.E25 61.77,38.94 ; U2.4 76.79,59.06 ; U2.4 v1(76.79,55.71) ; U2.4 77.45,57.62 ; C98.1 33.42,42.63 v1(33.74,42.63) 34.18,42.19 C101.1 ; P501.G11 59.26,23.66 v1(59.26,23.7) 59.23,23.7 P501.H12 P501.J11 P501.K12 ; 33.48,44.5 C58.1 32.95,43.96 ; CN4.1 21.8,54.44 ; 27.41,35.26 26.63,35.26 ; v1(63.03,32.59) v1(61.76,31.32) v1(60.49,30.05) v1(59.22,31.32) v1(57.95,30.05) v1(56.68,31.32) ; v1(53.17,50.76) 53.93,50.76 ; v1(53.17,50.76) 52.4,50.76 ; v1(53.17,50.76) 53.17,49.96 ; P501.D2 v4(64.37,11.36) ; P501.D2 v1(65.57,9.73) P501.B2 v1(68.11,9.73) ; P501.E34 P501.F33 P501.G32 P501.H33 P501.J32 P501.K33 ; 41.48,21 R9.2 ; R9.2 42.25,21.8 ; R9.2 40.72,21.8 ; 35.77,54.7 C22.1 v1(35.95,54.12) ; C148.2 17.01,5.04 ; C148.2 16.21,5.83 ; C148.2 v1(16.21,4.91) ; 8.7,28.72 C183.2 ; C183.2 9.86,29.73 ; C183.2 11.02,28.72 ; U16.2 8.21,40.34 ; v1(27.84,45.68) C90.1 ; 38.32,44.64 C204.1 ; C204.1 v1(38.33,45.55) 38.33,45.55 C26.1 ; C204.1 38.85,45.17 ; 71.46,20.79 C91.2 70.65,20.02 ; 47.32,54.13 C219.1 48.48,55.13 ; U4.2 52.02,51.27 52.15,51.14 v1(52.15,50.89) ; 76.56,22.75 R73.1 76.03,22.22 ; v1(63.07,59.26) 64.3,58.02 P501.D39 P501.C40 ; P501.B38 P501.A37 ; C12.1 38.05,44.15 ; 71.94,24.66 R79.2 72.47,24.13 ; C165.2 12.84,29.31 ; C165.2 11.84,28.15 ; C165.2 12.84,27 ; C2.2 25.67,39.04 ; C2.2 23.77,39.04 ; C2.2 v1(24.72,39.07) 24.72,39.9 ; 72.19,32.41 R80.1 72.73,32.94 ; v1(68.11,50.37) v1(66.84,51.64) v1(65.57,50.37) ; 35.64,55.2 C5.1 ; v1(51.26,55.96) 52.02,55.96 ; v1(51.26,55.96) 51.26,55.16 ; v1(51.26,55.96) 50.49,55.96 ; P501.B3 v4(66.76,11.92) ; P501.B3 P501.A4 ; P501.B3 v1(65.57,13.54) v1(64.3,12.27) P501.E4 61.8,12.3 v1(61.8,12.27) ; P501.H9 60.49,18.62 v1(60.53,18.62) ; 20.66,36.43 C61.2 ; C61.2 21.61,37.33 ; C61.2 19.7,37.33 ; 31.86,54.12 C29.1 31.32,54.66 ; C122.1 v1(36.53,54.56) ; 32.85,27.55 C72.1 ; v1(53.29,55.13) 54.44,55.13 ; v1(53.29,55.13) 53.29,54.13 ; v1(53.29,55.13) 52.13,55.13 ; v1(12.91,29.68) 14.37,31.14 19.23,31.14 20.06,31.96 v1(20.27,31.96) 20.4,31.84 C103.2 ; P501.A36 v1(66.84,52.91) P501.C36 ; 47.45,53.97 v1(47.45,53.17) 46.69,53.17 ; 70.31,47.2 v1(71.07,47.2) ; v1(71.07,47.2) 71.84,47.2 ; v1(71.07,47.2) 71.07,48 ; 43.26,25.48 43.26,26.25 ; 43.26,26.25 42.46,26.25 ; 43.26,26.25 43.26,27.01 ; 37.8,49.7 C54.1 37.27,49.17 ; C119.2 12.54,41.93 ; 33.48,54.72 C128.1 32.8,54.12 ; U17.PAD 36.86,15.9 U17.6 36.86,18.36 ; C142.2 v1(24.4,14.82) ; v1(26.14,47.96) 25.81,47.96 ; v1(66.84,36.4) P501.C21 v1(64.3,36.4) ; 35.73,47.74 C36.1 36.26,47.2 ; 31.65,21.93 R50.1 ; R50.1 32.66,20.87 ; R50.1 32.66,22.98 ; 75.52,59.06 U2.3 v1(75.52,55.71) ; 77.07,24.66 R70.1 76.54,24.13 ; 36.26,49.03 C49.1 35.73,48.5 ; 35.78,49.69 v1(36,49.69) C52.1 36.26,49.16 ; 48.52,55.49 v1(49.48,55.49) ; v1(49.48,55.49) 49.48,54.59 ; v1(49.48,55.49) 50.43,55.49 ; v1(64.3,44.02) v1(65.57,45.29) P501.B30 v1(68.11,45.29) ; 36.26,50.99 C55.1 v1(36,50.45) 35.79,50.45 ; P501.K27 P501.J26 P501.H27 P501.G26 P501.F27 v1(63.03,44.02) ; C109.1 35.01,44.5 ; v1(68.11,28.78) v1(66.84,27.51) v1(65.57,28.78) ; P501.A25 v1(66.84,41.48) 65.61,40.24 v1(65.61,40.21) ; v1(68.11,30.05) v1(66.84,31.32) v1(65.57,30.05) v1(64.3,28.78) ; 71.07,33.65 v1(71.07,32.85) 71.84,32.85 ; P501.F12 60.53,22.46 v1(60.53,22.43) ; 10.68,5.44 U5.6 10.68,7.89 v4(10.75,7.96) U5.PAD ; 66.88,2.59 v1(66.88,3.39) ; v1(66.88,3.39) 66.12,3.39 ; v1(66.88,3.39) 67.65,3.39 ; C50.1 38.56,49.7 ; 71.07,37.77 v1(71.07,38.57) ; v1(71.07,38.57) 70.31,38.57 ; v1(71.07,38.57) 71.84,38.57 ; 47.83,10.35 47.83,11.01 ; 47.83,11.01 46.38,11.01 ; 47.83,11.01 49.28,11.01 ; C160.1 28.59,48.75 ; C160.1 28.06,49.29 ; C160.1 28.06,48.22 ; 31.96,55.2 C7.5 ; v1(63.07,21.16) 63.04,21.16 P501.E10 v1(61.76,19.89) P501.G8 ; 37.51,28.79 C65.1 36.97,29.32 ; C169.1 39.52,22.27 ; C169.1 38.56,23.17 ; C169.1 37.61,22.27 ; 26.46,45.01 C156.1 25.63,45.01 ; 26.46,45.01 26.7,45.01 ; 26.46,45.01 v1(26.47,45.02) ; C103.2 21.54,32.6 ; C103.2 21.54,31.07 ; 37.06,41.28 C33.1 v1(36.53,41.36) ; P501.G35 P501.H36 P501.J35 P501.K36 ; P501.A24 v1(66.84,37.67) P501.C24 P501.D25 ; v1(32.11,27.44) 31.83,27.72 C70.1 ; 30.56,54.66 C53.1 30.03,54.12 ; 34.24,54.66 C121.1 v1(34.45,54.14) ; U18.9 50.23,60.54 v1(50.11,60.66) U18.PAD ; P501.A9 v1(66.84,21.16) P501.C9 P501.D10 ; 61.77,38.94 v1(61.8,38.94) ; 61.77,38.94 P501.F24 P501.G23 P501.H24 57.99,37.7 v1(57.99,37.67) ; 68.88,18.62 68.51,18.62 ; 28.21,51.17 C46.1 28.75,50.63 ; 7.13,45.31 C112.2 6.13,44.15 ; 36.53,44.5 C206.1 37.06,43.96 ; C26.1 38.85,45.93 ; C9.5 25.74,54.95 ; U18.PAD 51.38,62.69 ; U18.PAD 48.73,60.04 U18.6 ; v1(64.3,32.59) P501.C20 v1(66.84,32.59) ; v1(63.03,55.45) P501.D37 v1(65.57,56.72) ; P501.J29 P501.K30 ; 61.77,35.13 v1(61.8,35.13) ; 61.77,35.13 v1(63.03,36.4) ; U7.PAD 34.89,35.01 ; P501.F36 60.53,52.94 v1(60.53,52.91) ; v1(63.03,28.78) v1(61.76,27.51) v1(60.49,26.24) v1(59.22,27.51) P501.J14 P501.K15 ; 28.75,49.87 C161.1 28.21,49.34 ; R93.1 74.25,49.2 ; v1(61.92,23.7) 61.92,23.85 P501.E13 ; 9.14,37.8 C126.2 ; 49.28,13.55 U14.2 46.38,13.55 ; 23.53,42.81 22.23,44.1 22.23,45.73 22.56,46.06 24.87,46.06 v4(24.95,45.98) ; 26.36,47.43 C97.1 26.36,48.35 26.21,48.5 ; 8.97,37.42 8.97,36.66 8.17,36.66 ; 39.32,52.41 C10.1 ; C94.1 35.77,44.5 ; U19.6 18.04,58.94 ; 27.01,52.41 C9.1 ; Y1.3 19.07,32.42 ; v1(65.57,44.02) v1(66.84,42.75) v1(68.11,44.02) ; 76.79,32.94 R117.1 77.32,32.41 ; 76.82,34.31 R81.1 76.28,34.85 ; C5.7 v1(34.88,56.22) ; 29.93,54.31 C199.1 29.16,55.11 ; P501.B39 P501.A40 ; v1(68.11,49.1) 66.88,47.86 v1(66.88,47.83) ; v1(60.53,45.29) 60.53,45.32 v1(61.76,46.56) P501.E31 ; v1(68.11,23.7) v1(66.84,22.43) v1(65.57,23.7) P501.D13 ; C159.1 v1(25.76,49.23) 25.67,49.23 ; v1(60.49,13.54) P501.F3 ; P501.J40 P501.H39 P501.J38 P501.K39 ; 34.4,28.09 C77.1 33.86,27.55 ; R52.1 23.12,55.71 ; R52.1 22.12,54.66 ; R52.1 22.12,56.77 ; C64.1 v1(27.13,28.09) 27.07,28.03 19.97,28.03 18.24,26.3 18.24,23.66 18.13,23.28 18.05,23.24 ; C12.7 v1(38.84,43.14) ; P501.G29 P501.H30 57.99,45.32 v1(57.99,45.29) ; C10.5 38.05,54.95 ; 76.8,41.66 U12.11 ; C68.N v1(43.01,16.98) ; 24.82,30.95 C81.1 25.35,30.41 ; P501.B31 P501.C32 ; P501.K21 P501.J20 P501.H21 60.49,33.86 v1(60.53,33.86) ; 8.97,31.71 8.97,32.47 ; 8.97,31.71 v3(8.97,30.95) ; 8.97,31.71 8.17,31.71 ; C76.N v1(45.42,31.33) ; 70.65,18.5 C89.2 ; U8.4 14.87,26.11 ; C7.7 v1(31.48,56.73) ; C59.1 38.63,39.86 ; 72.73,47.29 R120.1 72.19,46.76 ; C57.1 34.24,44.5 ; 76.8,27.31 U13.11 ; C7.1 30.69,57.74
  TOP w0.508: 47.44,6.94 v4(48.6,6.94) ; v4(48.6,6.94) 48.6,8.3 ; v4(48.6,6.94) 48.6,5.58 ; v4(48.6,6.94) 49.75,6.94 ; 22.56,59.29 C222.N 23.51,60.66 ; v1(68.11,49.1) 68.79,49.1 ; 17.73,9.79 R38.2 16.68,8.78 ; U10.6 11.38,52.92 v1(11.64,52.66) U10.PAD v1(12.4,52.66) 12.65,52.92 U10.3 15.96,52.92 ; C228.2 36.16,59.65 ; C228.2 35.01,58.29 ; C228.2 33.85,59.65 ; P501.A5 68.88,14.81 ; 46.18,31.33 v1(45.42,31.33) ; 19.58,40.2 C180.2 18.57,41.36 ; 14.18,59.29 C186.N 13.23,60.66 ; 17.1,22.34 C27.2 ; C27.2 18.05,23.24 ; C27.2 16.15,23.24 ; P501.J1 57.95,9.05 ; 15.58,40.83 R58.2 14.62,39.93 ; P501.K24 55.92,38.94 ; 44.02,31.33 v1(44.66,31.33) C76.N ; C163.2 47.2,44.84 ; C163.2 46.04,43.84 ; C163.2 48.35,43.84 ; v1(68.11,50.37) 68.79,50.37 ; C262.2 50.89,43.84 ; C262.2 48.58,43.84 ; C262.2 49.74,44.84 ; P501.K27 55.92,42.75 ; v1(68.11,30.05) 68.79,30.05 ; 8.07,46.25 C48.2 ; 26.87,11.64 C226.2 ; C226.2 28.02,13 ; C226.2 29.18,11.64 ; v1(68.11,35.13) 68.79,35.13 ; 14.69,45.32 C13.2 13.73,46.22 ; 46.64,33.61 C261.2 ; C261.2 47.64,32.46 ; C261.2 47.64,34.77 ; P501.A40 68.88,59.26 ; C178.2 13.07,22.84 ; C178.2 13.07,20.98 ; C178.2 12.17,21.93 ; P501.A25 68.88,40.21 ; 40.72,18.35 C167.N 41.67,16.98 ; C24.2 39.51,24.49 ; C24.2 39.51,26.73 ; C24.2 v1(39.83,25.61) 40.48,25.61 ; 17.35,40.83 R48.2 18.31,39.93 ; 8.53,15.33 C31.N ; C31.N 10.43,15.33 ; C31.N 9.48,16.7 ; 8.7,21.61 C149.2 ; C149.2 11.02,21.61 ; C149.2 9.86,20.61 ; v1(68.11,44.02) 68.79,44.02 ; 27.25,56.85 C231.2 28.4,55.49 ; R43.1 18.92,56.28 ; R43.1 17.86,57.29 ; R43.1 16.81,56.28 ; P501.K21 55.92,35.13 ; 39.57,56.85 40.72,56.85 ; P501.A8 68.51,18.62 68.53,18.63 68.88,18.63 ; C76.N 45.04,29.96 ; C76.N 45.04,32.7 ; P501.K30 55.92,46.56 ; P501.K36 55.92,54.18 ; v1(63.03,9.73) 63.03,9.05 ; P501.E40 63.03,60.02 ; v3(12.53,15.33) 12.53,16.7 ; v3(12.53,15.33) 11.57,15.33 ; v3(12.53,15.33) 13.48,15.33 ; P501.G1 60.49,9.05 ; 43.39,18.35 C68.N v1(43.77,16.98) 44.53,16.98 ; C166.2 8.6,21.61 ; C166.2 7.45,20.61 ; C166.2 6.29,21.61 ; v1(68.11,28.78) 68.79,28.78 ; v1(65.57,9.73) 66.15,9.15 ; P501.A37 68.88,55.45 ; P501.C40 65.57,60.02 ; P501.K39 56.01,57.99 ; v1(68.11,24.97) 68.79,24.97 ; 20.08,51.66 C164.2 19.08,50.5 ; P501.A36 68.88,54.18 ; 42.12,16.98 v1(43.01,16.98) ; P501.K15 55.92,27.51 ; P501.K9 56.01,19.89 ; v1(68.11,23.7) 68.79,23.7 ; P501.K3 56.01,12.27 ; 41.72,45.81 C230.2 ; C230.2 42.88,44.45 ; C230.2 44.04,45.81 ; P501.K33 55.92,50.37 ; 31.39,16.98 C170.N ; v1(68.11,9.73) 68.11,9.05 ; 56.22,23.26 56.65,23.7 P501.K12 ; C34.2 12.92,46.25 ; v1(68.11,45.29) 68.79,45.29 ; P501.A9 68.88,19.89 ; P501.A4 68.88,13.54 ; v1(68.11,33.86) 68.79,33.86 ; P501.A24 68.88,38.94 ; v1(56.68,31.32) 56.01,31.32 ; P501.K2 55.92,11
  TOP w0.762: 31.89,4.79 C181.2 32.89,3.63 ; 37.15,6.94 C227.2 38.31,5.58 ; 2.61,11.23 RX_B.4 5.51,9.67 ; 13.42,23.2 v1(13.42,23.96) v1(13.42,24.6) U8.PAD v1(13.42,25.23) v1(13.42,25.74) 13.42,26.36 ; 28.02,5.58 C225.2 26.87,6.94 ; 15.32,16.62 v1(15.32,16.09) C96.N 13.95,15.71 ; 33.04,3.63 C220.2 34.05,4.79
  TOP w1.016: TX_A.4 5.51,49.16 ; TX_A.4 2.61,47.6 ; TX_A.4 2.61,50.73 ; TX_B.4 5.51,35.96 ; TX_B.4 2.61,34.39 ; TX_B.4 2.61,37.52 ; RX_A.2 2.61,33.07 ; RX_A.2 2.61,29.95 ; RX_A.2 5.51,31.51 ; RX_B.2 2.61,19.99 ; RX_B.2 2.61,16.87 ; RX_B.2 5.51,18.43 ; TX_B.2 2.61,46.28 ; TX_B.2 2.61,43.16 ; TX_B.2 5.51,44.72 ; 5.51,57.93 TX_A.2 2.61,56.36 ; 25.28,29.3 v1(24.59,29.3) C23.2 ; 2.61,24.31 RX_A.4 2.61,21.19
  TOP w1.27: U10.PAD 12.02,54.7
  L9_AGND w0.254: v3(75.65,30.57) v2(75.14,30.57)
  BOTTOM w0.203: v3(65.75,30.56) 65.75,30.44 65.24,29.93 U3.4 ; v3(68.03,51.65) 68.03,51.55 67.52,51.04 U6.4
  BOTTOM w0.254: v3(29.79,25.48) 29.28,25.48 29.1,25.29 U100.16 29.1,25.03 ; U100.31 30.38,17.28 v3(30.94,16.72) ; U100.18 30.38,23.78 30.94,24.34 v3(30.94,24.47) ; 29.1,16.03 U100.33 29.1,15.76 29.28,15.57 v3(29.79,15.57) ; v3(32.33,16.08) 32.33,15.59
  BOTTOM w0.305: U3.9 U3.8 62.58,30.83 ; U3.9 U3.10 ; U3.9 62.57,31.33 ; 14.69,20.51 R31.2 14.15,21.04 ; v3(8.39,29.67) 8.39,30.41 ; v3(8.39,29.67) 8.39,28.93 ; v3(8.39,29.67) 7.34,29.67 ; v3(8.39,29.67) 9.45,29.67 ; 19,15.43 C146.2 v3(18.81,15.96) 18.37,15.96 ; 18.37,16.72 v3(18.81,16.72) C131.2 ; v3(72.34,30.44) 73.14,30.44 ; v3(72.34,30.44) 72.34,29.68 ; v3(72.34,30.44) 72.34,31.2 ; 20.27,27.61 v3(20.27,27.26) C144.2 19.74,27.07 ; J1.4 36.18,26.75 ; J1.4 34.82,25.39 ; J1.4 37.54,25.39 ; C138.2 18.82,19.76 v3(18.81,19.77) ; U3.12 63.44,33.47 ; U3.12 62.59,32.83 ; U3.12 U3.11 ; R138.2 6.3,15.22 ; R138.2 5.76,14.68 ; R138.2 6.83,14.68 ; v3(33.61,15.07) 34.37,15.07 ; v3(33.61,15.07) 33.61,14.27 ; v3(33.61,15.07) 32.85,15.07 ; 27.68,39.71 v3(28.21,39.71) 28.21,39.18 ; CC02.1 75.84,29.56 ; CC02.1 75.84,27.25 ; CC02.1 76.84,28.41 ; 18.37,17.99 18.62,18.25 v3(18.81,18.25) C137.2 ; 39.83,25.39 J1.5 42.54,25.39 ; 26,51.42 C113.1 ; v3(26.04,52.18) C120.1 26.54,52.71 ; 18.47,23.52 C133.2 ; 5.76,27.76 R121.2 ; R121.2 6.3,28.3 ; R121.2 6.83,27.76 ; 28,53.62 C35.1 v3(28.53,54.21) ; v3(32.33,16.08) C212.2 ; C4.1 21.1,60.88 ; C4.1 19.19,60.88 ; C4.1 20.15,61.78 ; 27.21,43.23 C51.1 v3(26.64,43.76) ; C191.1 v3(28.55,42.26) C192.1 27.64,42.26 ; 64.24,34.39 U3.13 63.69,33.63 ; C179.2 25.8,13.42 ; v4(66.76,11.92) 67.49,12.66 ; 25.93,38.63 C60.1 26.5,38.1 ; 65.89,54.72 U6.13 66.52,55.52 ; 31.57,15.61 C210.2 ; 68.6,60.91 R57.2 ; R57.2 69.6,61.96 ; R57.2 68.6,63.01 ; U3.10 62.57,31.83 ; U3.10 U3.11 ; 25.98,48.6 C127.1 ; v3(22.56,29.57) 22.56,29.05 C197.2 ; 71.33,47.96 v3(71.33,48.73) 72.13,48.73 ; RC12.1 76.84,25.99 ; RC12.1 75.84,24.94 ; RC12.1 75.84,27.05 ; C135.2 v3(21.04,27.2) 21.04,27.54 ; CR1.C 47.17,55.75 ; CR1.C 46.44,56.59 ; CR1.C 45.7,55.75 ; R18.1 29.55,57.78 ; R18.1 28.78,56.98 ; R18.1 30.31,56.98 ; 16.46,31.14 T100.1 17.2,30.09 ; 32.66,40.24 C32.1 32.66,39.18 ; 19,25.57 C147.2 18.47,25.04 ; 31.01,39.18 v3(31.01,39.71) ; R16.1 28.53,56.98 ; R16.1 27.77,57.78 ; R16.1 27,56.98 ; v3(16.46,15.83) 16.46,15.83 ; GND.1 55.68,63.46 ; GND.1 54.95,64.2 ; GND.1 54.21,63.46 ; GND.1 54.95,62.72 ; U100.16 29.61,25.05 ; C123.2 25.35,27.99 ; 65.24,28.73 U3.4 ; 25.63,46.03 v3(26.09,46.03) 26.51,46.03 ; CVREG2.1 65.55,25.65 ; CVREG2.1 64.6,24.75 ; CVREG2.1 63.64,25.65 ; C105.1 v3(25.19,29.02) ; 72.15,31.54 RT22.1 73.16,32.6 ; 27.64,27.99 C125.2 28.17,27.45 ; CVREG1.1 66.64,48.76 v3(66.96,48.45) ; 21.93,13.42 C136.2 ; v3(75.39,46.19) 76.19,46.19 ; v3(75.39,46.19) 75.39,45.42 ; v3(75.39,46.19) 75.39,46.95 ; 26.51,46.03 C38.1 ; 26.51,46.03 C158.1 ; C176.2 v3(26.88,27.58) ; 20.46,13.99 C145.2 v3(21.16,13.42) ; J1.2 41.18,31.75 ; J1.2 42.54,30.39 ; J1.2 41.18,29.03 ; J1.2 39.83,30.39 ; C139.2 18.75,22.75 18.37,23.14 ; 22.37,27.71 22.56,27.52 v3(22.56,27.2) C140.2 ; 22.69,13.42 C130.2 ; 64.92,52.92 U6.10 ; 36.96,54.12 C56.1 36.43,54.66 ; 13.18,26.66 T100.4 ; T100.4 14.66,26.66 ; T100.4 13.92,25.61 ; 64.92,53.42 U6.11 ; TP1.1 36.25,57.13 ; TP1.1 36.25,55.66 ; TP1.1 35.51,56.4 ; TP1.1 36.99,56.4 ; 74.59,48.15 RC1.1 ; RC1.1 76.7,48.15 ; RC1.1 75.65,47.15 ; R20.2 v3(29.99,40.98) ; v3(22.17,12.22) 22.2,12.25 C115.1 ; 64.92,52.42 U6.9 ; v3(33.61,26.37) 33.61,27.17 ; v3(33.61,26.37) 32.85,26.37 ; v3(33.61,26.37) 34.37,26.37 ; v3(24.59,27.2) 24.59,27.83 24.78,28.03 ; C129.2 25.04,13.42 ; 64.92,53.92 U6.12 65.72,54.43 ; C211.2 32.34,25.57 ; 29.7,26.95 C207.2 29.16,27.48 ; 34.82,30.39 J1.3 ; J1.3 36.18,29.03 ; J1.3 37.54,30.39 ; J1.3 36.18,31.75 ; v3(73.61,51.77) 74.41,51.77 ; v3(73.61,51.77) 73.61,51.01 ; v3(73.61,51.77) 73.61,52.54 ; 29.57,16.03 29.1,16.03 ; C104.1 v3(29.29,54.24) ; 18.47,24.28 C134.2 ; T102.4 14.66,11.06 ; T102.4 13.92,10.01 ; T102.4 13.18,11.06 ; 17.2,14.49 T102.1 16.46,15.55 ; 21.8,27.54 v3(21.8,27.2) C173.2 ; 14.69,22.59 R68.2 14.15,22.06 ; 74.99,53.68 RT1.2 74.08,52.73 ; C107.1 v3(21.09,30.49) ; C100.2 26.65,28.98 ; C100.2 26.12,29.51 ; C100.2 25.58,28.98 ; C73.1 27.26,37.3 ; C73.1 26.73,37.87 ; C73.1 27.79,37.87 ; 7.34,11.51 T103.5 ; T103.5 9.45,11.51 ; T103.5 8.39,10.77 ; T103.5 8.39,12.25 ; C6.1 35.67,54.66 ; C209.2 31.58,25.57 ; C151.2 v3(27.32,13.42) ; C117.1 34.88,54.66 ; 64.92,51.92 U6.8 ; C116.2 v3(25.46,12.25) ; U3.11 62.58,32.33 ; C150.2 28.4,27.48 ; C175.2 v3(26.12,27.58) ; 65.7,25.55 R7.1 ; C177.2 v3(26.56,13.42) ; C190.1 v3(21.44,10.78) ; C114.1 v3(31.55,42.5) ; 30.08,13.99 C153.2 29.55,13.46 ; 18.37,17.48 v3(18.81,17.48) C195.2 ; 29.57,25.03 29.1,25.03 ; U100.33 29.61,16.01 ; 29.61,39.18 v3(29.61,39.71)
  BOTTOM w0.508: T3.3 9.23,59.81 ; T3.3 9.23,57.45 ; T3.3 10.85,58.63 ; T3.3 7.6,58.63 ; C18.2 55.39,5.32 ; C18.2 C152.2 ; C18.2 56.36,6.44 ; 70.13,36.66 CIN22.1 71.14,37.82 ; 2.61,47.6 TX_A.4 ; TX_A.4 5.51,49.16 ; TX_A.4 2.61,50.73 ; 70.63,58.9 CIN11.1 69.63,57.74 ; RX_A.4 2.61,24.31 ; RX_A.4 2.61,21.19 ; RX_A.4 5.51,22.75 ; 2.61,11.23 RX_B.4 5.51,9.67 ; R69.1 65.47,64.73 ; R69.1 64.32,63.57 ; R69.1 64.32,65.88 ; R69.1 63.16,64.73 ; 39.49,5.23 C45.2 ; C45.2 39.49,7.13 ; C45.2 38.59,6.18 ; RX_B.2 5.51,18.43 ; RX_B.2 2.61,19.99 ; RX_B.2 2.61,16.87 ; CIN12.1 71.14,40.23 ; CIN12.1 71.14,37.92 ; CIN12.1 70.13,39.07 ; C152.2 56.36,8.98 ; C152.2 55.39,10.09 ; TX_B.2 5.51,44.72 ; TX_B.2 2.61,43.16 ; TX_B.2 2.61,46.28 ; 2.61,56.36 TX_A.2 5.51,57.93 ; U11.6 v4(48.21,8.72) 47.96,8.72 v4(47.33,8.09) 46.69,8.72 v4(46.44,8.72) U11.3 ; CIN21.1 70.63,61.31 ; CIN21.1 69.63,60.16 ; CIN21.1 70.63,59 ; 39.71,8.04 R44.1 ; R44.1 38.65,9.04 ; R44.1 40.72,9.04 ; 58.63,35.14 CO5.1 ; TX_B.4 2.61,37.52 ; TX_B.4 2.61,34.39 ; TX_B.4 5.51,35.96 ; T4.1 9.23,36.45 ; T4.1 7.6,35.26 ; T4.1 9.23,34.08 ; T4.1 10.85,35.26 ; RX_A.2 5.51,31.51 ; RX_A.2 2.61,33.07 ; RX_A.2 2.61,29.95 ; CF4.1 57.36,36.53
  BOTTOM w0.635: 54.86,55.97 CF2.1 ; CF2.1 57.57,55.97 ; CF2.1 56.22,54.81 ; 57.65,55.97 CF1.1 ; CF1.1 59.01,54.81 ; CF1.1 60.37,55.97 ; CO4.1 53.42,54.58 ; CO4.1 54.78,53.43 ; CO4.1 52.06,53.43 ; CO1.1 63.16,53.43 ; CO1.1 60.44,53.43 ; CO1.1 61.8,54.58 ; CO2.1 60.37,53.43 ; CO2.1 59.01,54.58 ; CO2.1 57.65,53.43 ; CO3.1 57.57,53.43 ; CO3.1 54.86,53.43 ; CO3.1 56.22,54.58 ; 52.06,55.97 CF3.1 ; CF3.1 53.42,54.81 ; CF3.1 54.78,55.97
  BOTTOM w0.762: v3(52.41,36.53) 51.72,36.53
  BOTTOM w1.016: CO8.1 CO7.1 ; CO8.1 50.25,35.11 ; CO8.1 48.72,33.99 ; CO7.1 CO6.1 ; CO7.1 v3(53.04,34.5) v3(53.04,36.03) v3(53.04,36.53) ; v3(53.04,36.53) v3(53.68,36.53) CF4.1 v3(55.83,34.5) CO6.1 ; v3(53.04,36.53) v3(52.41,36.53) ; 47.33,10.37 v4(47.33,9.36) v4(47.33,8.72) v4(47.33,8.09) v4(47.33,7.45) v4(47.33,6.82) 47.33,5.8 ; 59.95,33.99 CO5.1 v3(58.5,33.99) v3(57.99,33.99) CO6.1
  vias: v1(5.16,52.54) v1(5.92,42.88) v1(5.95,39.18) v1(6.05,46.95) v1(6.25,41.56) v1(6.3,50.12) v1(6.43,57.62) v1(6.43,55.08) v1(6.43,48.09) v1(6.43,45.55) v1(6.43,37.93) v1(6.43,35.39) v1(6.43,32.85) v1(6.43,31.59) v1(6.43,30.31) v1(6.43,27.77) v1(6.43,17.61) v1(6.43,14.44) v1(6.43,10.63) v1(6.65,44.64) v1(6.56,29.04) v1(6.94,21.93) v1(6.94,21.29) v1(7.42,37.36) v1(7.7,19.52) v1(7.7,17.61) v1(7.7,15.71) v1(7.7,14.44) v1(7.96,21.93) v1(7.96,21.29) v1(8.21,29.68) v1(8.34,28.79) v1(8.72,46.69) v1(8.72,45.93) v1(8.97,62.06) v1(8.97,59.52) v1(8.97,57.62) v1(8.97,55.08) v1(9.1,16.09) v1(9.1,15.33) v1(9.1,14.56) v1(9.35,21.93) v1(9.35,21.29) v1(9.73,46.69) v1(9.73,45.93) v1(9.86,16.09) v1(9.86,15.33) v1(9.86,14.56) v1(10.24,19.52) v1(10.24,17.61) v1(10.37,21.93) v1(10.37,21.29) v1(10.67,5.19) v1(10.88,55.08) v1(11,53.43) v1(11,52.66) v1(11,51.9) v1(11,51.14) v1(11.13,32.66) v1(11.26,46.69) v1(11.26,45.93) v1(11.26,34.12) v1(11.51,62.06) v1(11.51,59.52) v1(11.51,57.62) v1(11.51,29.68) v1(11.51,28.91) v1(11.51,28.15) v1(11.51,27.39) v1(11.51,26.63) v1(11.51,22.06) v1(11.51,20.79) v1(11.64,53.43) v1(11.64,51.9) v1(11.64,51.14) v1(12.15,19.52) v1(12.15,17.61) v1(12.15,16.09) v1(12.15,15.33) v1(12.15,14.56) v1(12.27,46.69) v1(12.27,45.93) v1(12.4,53.43) v1(12.4,51.9) v1(12.4,51.14) v1(12.65,26.63) v1(12.91,25.74) v1(12.91,25.23) v1(12.91,24.6) v1(12.91,23.96) v1(12.91,23.07) v1(12.91,16.09) v1(12.91,15.33) v1(12.91,14.56) v1(13.04,53.43) v1(13.04,52.66) v1(13.04,51.9) v1(13.04,51.14) v1(13.42,44.28) v1(13.42,26.63) v1(13.42,20.15) v1(13.42,18.81) v1(13.42,6.18) v1(13.54,23.07) v1(13.8,61.43) v1(13.8,60.66) v1(13.8,59.9) v1(13.92,25.74) v1(13.92,25.23) v1(13.92,24.6) v1(13.92,23.96) v1(14.05,57.62) v1(13.99,34.12) v1(14.05,26.63) v1(14.13,20.74) v1(14.18,23.07) v1(14.31,46.57) v1(14.31,45.93) v1(14.31,29.68) v1(14.56,61.43) v1(14.56,60.66) v1(14.56,59.9) v1(14.56,16.09) v1(14.56,15.33) v1(14.69,45.04) v1(14.81,26.63) v1(15.07,46.57) v1(15.07,45.93) v1(15.19,34.12) v1(15.19,10.25) v1(15.32,29.68) v1(15.32,15.33) v1(15.96,41.74) v1(16.08,41.11) v1(16.08,16.09) v1(16.08,15.33) v1(16.34,54.95) v1(16.34,53.43) v1(16.59,59.01) v1(16.59,57.62) v1(16.59,9.99) v1(16.72,23.58) v1(16.72,22.95) v1(17.1,32.98) v1(17.1,31.84) v1(17.35,8.85) v1(17.48,56.6) v1(17.48,41.11) v1(17.48,23.58) v1(17.48,22.95) v1(17.86,58.25) v1(17.86,4.91) v1(18.12,10.37) v1(18.12,8.85) v1(18.24,55.97) v1(18.37,32.98) v1(18.37,31.84) v1(19,67.65) v1(19,66.25) v1(19.26,41.87) v1(19.26,41.36) v1(19.26,40.85) v1(19.26,36.28) v1(19.77,54.44) v1(19.77,52.54) v1(19.77,51.01) v1(19.77,50.5) v1(19.77,50) v1(19.77,4.91) v1(19.89,41.87) v1(19.89,41.36) v1(19.89,40.85) v1(20.4,51.01) v1(20.4,50.5) v1(20.4,50) v1(21.16,67.65) v1(21.16,66.25) v1(21.16,36.03) v1(21.8,56.09) v1(22.18,61.43) v1(22.18,60.66) v1(22.18,59.9) v1(22.31,4.91) v1(22.43,55.33) v1(22.94,61.43) v1(22.94,60.66) v1(22.94,59.9) v1(23.58,58.89) v1(23.58,55.71) v1(23.7,67.65) v1(23.7,66.25) v1(23.96,29.8) v1(23.96,29.3) v1(23.96,28.79) v1(24.21,57.62) v1(24.59,29.8) v1(24.59,28.79) v1(24.85,41.11) v1(25.35,30.31) v1(25.53,50.12) v1(25.74,67.65) v1(25.74,66.25) v1(25.74,39.07) v1(26.12,50.12) v1(27.01,52.28) v1(27.51,12.4) v1(27.51,11.64) v1(27.51,10.88) v1(27.51,7.58) v1(27.51,6.94) v1(27.51,6.31) v1(27.77,67.65) v1(27.77,66.25) v1(27.89,57.62) v1(27.89,56.85) v1(27.89,56.09) v1(28.2,48.75) v1(28.28,50.63) v1(28.28,49.87) v1(28.4,45.04) v1(28.48,46.59) v1(28.53,12.4) v1(28.53,11.64) v1(28.53,10.88) v1(28.53,7.58) v1(28.53,6.94) v1(28.53,6.31) v1(28.66,14.06) v1(28.91,57.62) v1(28.91,56.85) v1(28.91,56.09) v1(29.16,55.33) v1(29.16,54.57) v1(29.16,51.9) v1(29.8,67.65) v1(29.8,66.25) v1(29.93,51.9) v1(29.93,44.08) v1(30.56,54.19) v1(30.94,18.88) v1(30.94,17.87) v1(30.94,16.98) v1(31.2,51.9) v1(31.2,22.95) v1(31.2,21.93) v1(31.2,20.91) v1(31.32,54.19) v1(31.58,44.09) v1(31.57,4.02) v1(31.57,3.25) v1(31.83,67.65) v1(31.83,66.25) v1(31.96,17.74) v1(31.96,16.98) v1(31.96,16.21) v1(32.21,4.02) v1(32.21,3.25) v1(32.47,51.9) v1(32.59,23.33) v1(32.72,17.74) v1(32.72,16.98) v1(32.72,16.21) v1(32.85,44.03) v1(32.85,27.52) v1(33.48,44.03) v1(33.74,67.65) v1(33.74,66.25) v1(33.74,64.22) v1(33.73,4.02) v1(33.73,3.25) v1(34.24,51.65) v1(34.24,44.03) v1(34.37,27.14) v1(34.36,4.02) v1(34.36,3.25) v1(34.5,60.41) v1(34.5,59.65) v1(34.5,58.89) v1(34.88,23.33) v1(35.01,51.65) v1(35.51,60.41) v1(35.51,59.65) v1(35.51,58.89) v1(35.77,67.65) v1(35.77,66.25) v1(35.77,64.22) v1(35.77,44.03) v1(35.77,16.34) v1(36.02,51.65) v1(36.02,46.19) v1(36.02,45.55) v1(36.28,46.82) v1(36.28,44.92) v1(36.28,16.34) v1(36.78,51.65) v1(36.78,16.34) v1(36.91,23.96) v1(36.91,22.95) v1(36.91,21.93) v1(36.91,20.91) v1(37.29,16.34) v1(37.55,29.04) v1(37.8,67.65) v1(37.8,66.25) v1(37.8,64.22) v1(37.8,49.36) v1(37.8,7.58) v1(37.8,6.94) v1(37.8,6.31) v1(38.18,51.9) v1(38.18,50.63) v1(38.56,49.36) v1(38.69,39.33) v1(38.69,37.8) v1(38.69,36.28) v1(38.69,34.76) v1(38.69,33.23) v1(38.69,31.71) v1(38.82,7.58) v1(38.82,6.94) v1(38.82,6.31) v1(39.2,26.12) v1(39.2,25.61) v1(39.2,25.1) v1(39.83,67.65) v1(39.83,66.25) v1(39.83,64.22) v1(39.83,26.12) v1(39.83,25.1) v1(40.09,51.9) v1(40.09,50.63) v1(40.09,29.04) v1(40.21,57.62) v1(40.21,56.85) v1(40.21,56.09) v1(40.34,17.74) v1(40.34,16.98) v1(40.34,16.21) v1(40.72,20.79) v1(40.72,18.88) v1(41.1,17.74) v1(41.1,16.98) v1(41.1,16.21) v1(41.23,57.62) v1(41.23,56.85) v1(41.23,56.09) v1(41.86,67.65) v1(41.86,66.25) v1(41.86,64.22) v1(41.99,30.82) v1(42.37,46.57) v1(42.37,45.81) v1(42.37,45.04) v1(42.37,25.23) v1(42.63,42.38) v1(42.88,12.15) v1(42.88,11.01) v1(42.88,9.86) v1(43.01,17.74) v1(43.01,16.21) v1(43.26,37.93) v1(43.26,36.66) v1(43.26,18.88) v1(43.39,46.57) v1(43.39,45.81) v1(43.39,45.04) v1(43.52,25.23) v1(43.77,17.74) v1(43.77,16.21) v1(43.9,62.19) v1(43.9,58.63) v1(43.9,55.08) v1(43.9,51.52) v1(44.53,13.93) v1(44.53,12.66) v1(44.66,30.57) v1(44.81,32.09) v1(45.17,45.55) v1(45.17,43.65) v1(45.17,42.38) v1(45.17,41.11) v1(45.17,37.93) v1(45.17,36.66) v1(45.17,34.76) v1(45.42,32.09) v1(45.42,30.57) v1(45.55,12.28) v1(45.67,67.13) v1(45.8,11.01) v1(45.8,9.86) v1(45.8,4.28) v1(45.8,1.74) v1(46.31,52.54) v1(46.31,50.5) v1(46.44,48.73) v1(46.44,46.82) v1(46.44,30.95) v1(46.44,29.04) v1(46.44,26.5) v1(46.44,23.96) v1(46.44,22.06) v1(46.44,19.52) v1(46.44,16.98) v1(46.69,44.15) v1(46.69,43.52) v1(47.2,44.15) v1(47.2,43.52) v1(47.33,55.46) v1(47.71,44.15) v1(47.71,43.52) v1(47.83,9.86) v1(48.09,6.31) v1(48.34,30.95) v1(48.34,29.04) v1(48.34,26.5) v1(48.34,4.28) v1(48.34,1.74) v1(48.47,38.82) v1(48.47,38.31) v1(48.47,11.26) v1(48.85,61.93) v1(48.85,61.3) v1(48.84,60.66) v1(48.84,60.02) v1(48.98,48.73) v1(48.98,46.82) v1(48.98,18.88) v1(48.98,16.98) v1(49.1,7.58) v1(49.1,6.94) v1(49.1,6.31) v1(49.22,67.13) v1(49.23,44.15) v1(49.23,43.52) v1(49.48,61.93) v1(49.48,61.3) v1(49.48,60.66) v1(49.48,60.02) v1(49.74,44.15) v1(49.74,43.52) v1(49.87,11.01) v1(49.87,9.86) v1(50.11,61.93) v1(50.11,61.29) v1(50.11,60.02) v1(50.25,44.15) v1(50.25,43.52) v1(50.75,61.93) v1(50.75,61.29) v1(50.75,60.66) v1(50.75,60.02) v1(50.88,29.04) v1(50.88,26.5) v1(50.88,4.28) v1(50.88,1.74) v1(51.14,18.88) v1(51.26,54.44) v1(51.52,48.73) v1(51.52,46.82) v1(51.52,44.92) v1(51.52,43.27) v1(51.52,16.98) v1(52.15,63.71) v1(52.15,62.82) v1(52.78,67.13) v1(52.79,41.11) v1(53.29,53.3) v1(53.42,37.93) v1(53.42,36.03) v1(53.42,33.49) v1(53.42,30.95) v1(53.42,29.04) v1(53.42,16.85) v1(53.42,4.28) v1(53.42,1.74) v1(54.06,48.73) v1(54.06,46.82) v1(54.06,44.92) v1(54.06,43.01) v1(54.06,41.11) v1(54.06,20.79) v1(54.43,8.33) v1(54.43,6.81) v1(54.82,64.47) v1(54.95,55.08) v1(54.95,53.3) v1(55.07,60.28) v1(55.33,41.11) v1(55.33,37.93) v1(55.33,36.03) v1(55.33,33.49) v1(55.33,30.95) v1(55.33,29.04) v1(55.58,62.95) v1(55.58,61.68) v1(55.96,4.28) v1(55.96,1.74) v1(56.34,67.13) v1(56.46,8.33) v1(56.46,6.81) v1(56.72,57.99) v1(56.72,54.18) v1(56.72,50.37) v1(56.72,46.56) v1(56.72,42.75) v1(56.72,38.94) v1(56.72,35.13) v1(56.72,23.7) v1(56.68,16.08) v1(56.72,12.27) v1(56.72,11) v1(57.22,2.62) v1(57.49,64.47) v1(57.49,62.95) v1(57.49,61.68) v1(57.61,1.48) v1(57.86,49.1) v1(57.95,18.62) v1(57.95,14.81) v1(57.95,13.54) v1(57.99,59.26) v1(57.99,56.72) v1(57.99,52.91) v1(57.99,41.48) v1(57.99,33.86) v1(57.99,9.73) v1(58.49,8.33) v1(58.49,6.81) v1(59,50.37) v1(59.26,57.99) v1(59.26,54.18) v1(59.26,46.56) v1(59.26,42.75) v1(59.26,38.94) v1(59.26,35.13) v1(59.26,12.27) v1(59.26,11) v1(60.49,59.26) v1(60.53,56.72) v1(60.53,49.1) v1(60.53,41.48) v1(60.53,37.67) v1(60.53,9.73) v1(61.54,11) v1(61.8,57.99) v1(61.8,54.18) v1(61.8,50.37) v1(61.8,42.75) v1(63.07,51.64) v1(63.07,24.97) v1(63.07,17.35) v1(63.84,60.79) v1(64.09,65.24) v1(64.34,40.21) v1(64.34,21.16) v1(65.61,59.26) v1(65.61,38.94) v1(65.61,24.97) v1(65.61,19.89) v1(65.61,18.62) v1(65.74,49.11) v1(65.99,60.79) v1(66.88,65.24) v1(66.88,61.43) v1(66.88,57.99) v1(66.88,56.72) v1(66.88,17.35) v1(66.88,11) v1(68.15,59.26) v1(68.15,55.45) v1(68.15,54.18) v1(68.15,40.21) v1(68.15,38.94) v1(68.15,19.89) v1(68.15,18.62) v1(68.15,14.81) v1(68.15,13.54) v1(69.09,36.25) v1(69.55,58.63) v1(69.55,56.6) v1(69.55,54.57) v1(69.55,52.54) v1(69.55,50.63) v1(69.55,48.6) v1(69.55,46.57) v1(69.55,44.54) v1(69.55,42.5) v1(69.55,38.57) v1(69.68,67.01) v1(69.68,65.24) v1(69.68,63.46) v1(69.68,61.43) v1(70.06,40.6) v1(70.57,22.31) v1(71.07,36.79) v1(71.33,20.02) v1(71.33,18.5) v1(71.58,50.76) v1(71.71,59.65) v1(71.71,58.63) v1(71.71,56.6) v1(72.09,22.31) v1(72.47,24.6) v1(72.6,15.2) v1(72.6,13.17) v1(72.73,46.82) v1(72.73,32.47) v1(73.11,52.41) v1(73.49,38.95) v1(73.61,59.65) v1(73.74,46.82) v1(74,37.04) v1(74.25,48.73) v1(75.14,52.41) v1(75.14,50.76) v1(75.52,59.65) v1(75.52,24.6) v1(75.77,32.47) v1(76.03,22.69) v1(76.28,34.38) v1(76.54,24.6) v1(76.79,32.47) v1(76.92,59.65) v1(77.17,52.41) v1(77.17,50.76) v1(77.55,42.88) v1(77.55,40.6) v1(77.55,39.58) v1(77.55,37.55) v1(77.55,35.52) v1(77.55,32.98) v1(77.55,30.44) v1(77.55,28.53) v1(77.55,26.37) v1(77.55,23.83) v2(5.8,58.89) v2(5.8,56.35) v2(5.8,54.44) v2(5.8,49.36) v2(5.8,44.92) v2(5.8,41.11) v2(5.8,38.57) v2(5.8,36.66) v2(5.8,34.12) v2(5.8,31.58) v2(5.8,29.68) v2(5.8,20.15) v2(5.8,16.98) v2(5.8,10.63) v2(5.8,8.09) v2(6.3,15.45) v2(6.3,12.91) v2(7.07,32.22) v2(7.7,65.11) v2(7.7,58.89) v2(7.7,56.35) v2(7.7,54.44) v2(7.7,41.11) v2(7.7,39.84) v2(7.7,37.93) v2(7.7,34.76) v2(7.7,32.85) v2(8.34,16.98) v2(8.34,10.63) v2(8.97,34.12) v2(8.97,32.85) v2(9.48,44.03) v2(9.61,50) v2(10.24,58.89) v2(10.24,56.35) v2(10.24,54.44) v2(10.24,37.93) v2(10.24,34.12) v2(10.24,32.85) v2(10.24,31.58) v2(10.24,29.68) v2(10.24,26.5) v2(10.24,22.69) v2(10.24,20.15) v2(10.24,16.98) v2(10.24,6.18) v2(10.88,65.11) v2(10.88,63.33) v2(11.51,50) v2(12.15,58.89) v2(12.15,44.92) v2(12.15,42.38) v2(12.15,39.84) v2(12.15,36.66) v2(12.15,34.12) v2(12.15,32.85) v2(12.15,30.95) v2(12.15,27.77) v2(12.15,20.15) v2(12.15,6.18) v2(12.78,8.09) v2(13.42,65.11) v2(13.42,34.12) v2(13.42,32.85) v2(13.42,19.52) v2(13.42,16.98) v2(13.42,11.26) v2(13.54,15.1) v2(14.69,58.89) v2(14.69,56.35) v2(14.69,54.44) v2(14.69,50) v2(14.69,44.28) v2(14.69,42.88) v2(14.69,39.84) v2(14.69,36.66) v2(14.69,34.12) v2(14.69,32.85) v2(14.69,30.95) v2(14.66,17.08) v2(14.79,11.24) v2(15.19,26.63) v2(15.32,13.8) v2(15.32,8.09) v2(15.32,6.18) v2(15.45,65.11) v2(15.6,21.95) v2(15.6,21.14) v2(15.96,45.04) v2(15.96,42.88) v2(15.96,32.85) v2(16.46,27.64) v2(16.59,30.95) v2(16.59,23.96) v2(16.57,19.16) v2(16.57,17.61) v2(17.23,39.84) v2(17.23,36.66) v2(17.23,34.12) v2(17.86,50) v2(17.86,8.09) v2(17.86,6.18) v2(18.5,60.16) v2(18.5,54.44) v2(18.5,48.6) v2(18.5,10.88) v2(18.9,43.39) v2(19.77,67.65) v2(19.77,49.36) v2(19.77,44.28) v2(19.77,39.84) v2(19.77,36.66) v2(19.77,34.12) v2(20.4,63.33) v2(20.4,60.16) v2(20.4,57.62) v2(20.4,55.71) v2(20.4,12.79) v2(20.4,8.09) v2(20.4,6.18) v2(21.67,36.66) v2(21.67,34.12) v2(21.8,39.96) v2(21.93,48.6) v2(22.15,45.3) v2(22.31,67.65) v2(22.31,63.33) v2(22.31,58.89) v2(22.94,6.18) v2(23.58,63.97) v2(23.58,60.79) v2(24.21,36.66) v2(24.21,34.12) v2(24.21,8.98) v2(24.21,1.74) v2(24.59,45.3) v2(24.85,67.65) v2(25.48,60.79) v2(25.48,58.89) v2(25.48,3.64) v2(26.75,67.65) v2(26.75,12.53) v2(26.75,9.36) v2(26.75,6.18) v2(27.39,63.97) v2(27.39,60.79) v2(27.39,1.74) v2(28.02,62.06) v2(28.02,3.64) v2(28.15,36.79) v2(28.66,67.65) v2(29.29,58.89) v2(29.55,52.54) v2(29.93,63.97) v2(30.56,67.65) v2(30.64,58.02) v2(30.56,10.63) v2(30.56,8.72) v2(30.56,6.82) v2(30.94,54.95) v2(31.2,1.74) v2(31.83,62.06) v2(32.47,67.65) v2(32.47,63.97) v2(32.47,53.17) v2(32.72,20.02) v2(33.08,58.02) v2(33.1,27.14) v2(33.61,21.42) v2(33.74,62.06) v2(33.74,10.63) v2(33.74,8.72) v2(33.74,6.82) v2(33.74,1.74) v2(34.12,20.02) v2(34.37,67.65) v2(34.37,65.24) v2(34.37,16.72) v2(34.37,14.44) v2(34.88,54.95) v2(35.01,57.62) v2(35.39,42) v2(35.51,21.42) v2(36.02,54.95) v2(36.28,62.06) v2(36.28,19.39) v2(36.28,17.61) v2(36.28,11.9) v2(36.28,8.72) v2(36.53,50.12) v2(36.91,67.65) v2(36.91,65.24) v2(36.91,63.97) v2(36.91,1.74) v2(37.55,60.16) v2(38.05,29.42) v2(38.18,23.96) v2(38.18,22.56) v2(38.18,19.39) v2(38.18,17.61) v2(38.18,14.44) v2(38.18,2.37) v2(38.82,67.65) v2(38.82,62.06) v2(38.82,29.74) v2(38.82,8.72) v2(38.94,44.92) v2(39.45,65.24) v2(39.58,29.42) v2(40.09,60.16) v2(40.09,50) v2(40.72,67.65) v2(40.72,63.97) v2(40.72,31.58) v2(40.72,23.96) v2(40.72,22.56) v2(40.72,8.72) v2(40.72,6.82) v2(40.72,1.74) v2(41.03,36.69) v2(41.03,34.25) v2(41.13,38.59) v2(41.36,62.06) v2(41.36,58.25) v2(41.36,51.9) v2(41.36,14.44) v2(41.61,16.85) v2(41.86,45.17) v2(41.99,65.24) v2(41.99,18.63) v2(42.12,28.28) v2(42.19,29.85) v2(42.4,36.76) v2(42.63,60.16) v2(42.63,57.62) v2(42.88,50) v2(42.88,15.58) v2(43.26,22.06) v2(43.9,8.72) v2(43.9,6.82) v2(44,33.69) v2(44.02,24.09) v2(44.07,38.62) v2(44.1,32.78) v2(44.1,31.96) v2(44.53,44.03) v2(44.91,47.96) v2(45.29,17.74) v2(45.42,22.44) v2(45.67,19.77) v2(45.8,65.87) v2(45.8,62.7) v2(45.8,56.35) v2(46.44,3.01) v2(46.44,1.74) v2(47.07,14.82) v2(47.07,13.17) v2(47.2,18.25) v2(47.71,64.6) v2(47.71,62.06) v2(47.71,60.16) v2(47.71,58.25) v2(47.71,16.47) v2(48.6,44.41) v2(48.98,47.46) v2(48.98,3.01) v2(48.98,1.74) v2(49.61,28.41) v2(49.61,22.06) v2(49.61,14.82) v2(49.61,13.17) v2(50.25,48.09) v2(50.25,16.47) v2(50.5,28.41) v2(50.75,44.41) v2(51.24,19.74) v2(52.15,65.87) v2(52.15,44.41) v2(52.15,4.91) v2(52.15,3.01) v2(52.15,1.74) v2(52.79,40.6) v2(52.79,38.82) v2(52.79,35.39) v2(52.79,32.22) v2(52.79,30.31) v2(52.79,14.82) v2(52.79,6.18) v2(53.42,46.19) v2(53.42,13.17) v2(54.06,7.45) v2(54.69,29.04) v2(55.33,38.82) v2(55.33,35.39) v2(55.33,14.82) v2(55.33,3.01) v2(55.96,64.6) v2(55.96,51.9) v2(55.96,44.41) v2(56.01,41.64) v2(55.96,32.22) v2(56.6,66.51) v2(56.6,4.91) v2(57.23,57.62) v2(57.23,7.45) v2(57.87,48.09) v2(57.87,32.22) v2(58.5,51.9) v2(58.63,36.03) v2(59.14,41.36) v2(59.77,56.98) v2(59.77,47.46) v2(59.77,32.22) v2(60.15,18.37) v2(60.41,54.44) v2(60.41,39.2) v2(60.41,8.09) v2(61.04,48.09) v2(61.4,13.55) v2(61.68,62.06) v2(61.68,51.9) v2(62.82,41.36) v2(62.95,67.14) v2(62.95,56.98) v2(62.95,39.2) v2(62.95,37.93) v2(62.95,23.96) v2(62.95,1.74) v2(63.15,13.34) v2(63.17,16.47) v2(63.56,29.35) v2(63.58,65.87) v2(63.58,27.77) v2(63.58,22.31) v2(63.76,18.14) v2(64.22,62.06) v2(64.42,20.43) v2(64.52,15.02) v2(65.36,41.36) v2(65.49,67.14) v2(65.49,65.87) v2(65.49,37.93) v2(65.49,6.18) v2(65.49,4.28) v2(65.59,17.92) v2(65.59,15.5) v2(66.63,65.87) v2(66.76,62.06) v2(66.76,1.74) v2(66.91,37.04) v2(67.39,8.09) v2(67.39,6.18) v2(67.72,41.28) v2(67.77,48.02) v2(68.13,17.94) v2(68.13,15.5) v2(68.53,41.28) v2(68.59,48.02) v2(68.66,62.06) v2(68.94,22.21) v2(68.94,21.4) v2(69.3,67.65) v2(69.3,65.87) v2(69.35,37.02) v2(69.3,4.28) v2(69.3,1.74) v2(69.93,14.44) v2(69.93,12.53) v2(69.93,8.09) v2(70.44,19.26) v2(70.44,18.25) v2(70.44,16.34) v2(70.57,67.14) v2(71.2,65.87) v2(71.2,3.01) v2(72.34,26.37) v2(72.47,16.34) v2(72.47,14.44) v2(72.47,4.28) v2(72.47,1.74) v2(73.11,60.79) v2(73.11,57.62) v2(73.11,28.91) v2(73.61,30.44) v2(73.74,55.71) v2(74.12,50.25) v2(74.38,67.65) v2(74.63,27.39) v2(74.76,28.91) v2(75.01,16.34) v2(75.01,14.44) v2(75.01,1.74) v2(75.65,60.79) v2(75.65,57.62) v2(75.65,19.26) v2(75.65,12.53) v2(75.65,8.09) v2(75.65,5.55) v2(76.28,54.44) v2(76.28,51.9) v2(77.42,65.11) v2(77.42,62.7) v2(77.42,60.16) v2(77.42,57.62) v2(77.42,54.44) v2(77.42,24.85) v2(77.42,20.79) v2(77.42,19.26) v2(77.42,3.01) v3(6.3,27.89) v3(6.3,14.81) v3(6.81,58.63) v3(6.81,57.49) v3(7.07,48.09) v3(7.07,45.55) v3(7.07,43.65) v3(7.07,41.74) v3(7.07,38.57) v3(7.07,36.41) v3(7.07,35.39) v3(7.07,34.38) v3(7.07,33.36) v3(7.07,31.58) v3(7.07,25.87) v3(7.07,21.42) v3(7.07,18.88) v3(7.07,16.34) v3(7.07,9.99) v3(7.07,8.09) v3(7.32,46.44) v3(7.7,32.22) v3(7.7,30.95) v3(8.08,60.41) v3(8.08,33.36) v3(8.34,31.58) v3(8.97,64.6) v3(8.97,32.22) v3(8.97,31.58) v3(8.97,25.87) v3(8.97,23.96) v3(8.97,21.42) v3(8.97,18.88) v3(8.97,16.34) v3(9.23,60.41) v3(9.23,33.36) v3(9.61,48.09) v3(9.61,45.55) v3(9.61,31.58) v3(10.24,33.36) v3(10.24,32.22) v3(10.24,30.95) v3(10.37,60.41) v3(10.37,4.91) v3(10.5,15.33) v3(10.5,14.31) v3(10.5,13.29) v3(10.5,12.28) v3(10.5,11.26) v3(10.62,30.18) v3(10.62,29.3) v3(10.62,28.53) v3(10.62,27.77) v3(10.62,27.01) v3(10.88,26.12) v3(10.88,23.96) v3(10.88,21.42) v3(10.88,18.88) v3(10.88,16.34) v3(11.13,10.63) v3(11.26,34.88) v3(11.26,34.25) v3(11.26,33.36) v3(11.38,60.41) v3(11.38,59.27) v3(11.38,58.12) v3(11.51,64.6) v3(11.51,62.7) v3(11.51,32.85) v3(11.51,32.22) v3(11.51,31.58) v3(11.51,30.95) v3(11.51,15.33) v3(11.51,9.99) v3(11.64,26.12) v3(12.02,10.63) v3(12.15,51.27) v3(12.15,48.09) v3(12.15,45.55) v3(12.15,33.49) v3(12.15,32.22) v3(12.4,26.12) v3(12.53,30.57) v3(12.78,33.49) v3(12.78,32.85) v3(12.78,32.22) v3(12.78,31.58) v3(12.78,18.88) v3(12.78,16.34) v3(13.04,30.57) v3(13.04,26.76) v3(13.42,33.49) v3(13.42,32.22) v3(13.42,18.25) v3(13.42,6.82) v3(13.42,4.91) v3(13.54,42.5) v3(13.54,15.71) v3(13.8,23.96) v3(14.05,62.7) v3(14.05,32.85) v3(14.05,31.58) v3(14.56,15.71) v3(14.69,51.27) v3(14.69,48.09) v3(14.69,45.55) v3(14.69,43.65) v3(14.69,33.49) v3(14.69,32.22) v3(14.69,16.34) v3(14.81,27.14) v3(14.81,10.5) v3(15.32,33.49) v3(15.32,32.85) v3(15.32,32.22) v3(15.32,31.58) v3(15.58,27.01) v3(15.58,25.99) v3(15.58,15.83) v3(15.58,11.26) v3(15.58,10.37) v3(15.96,33.49) v3(15.96,32.22) v3(15.96,23.96) v3(16.59,62.7) v3(16.59,59.52) v3(16.59,53.81) v3(16.59,51.27) v3(16.59,48.09) v3(16.59,45.55) v3(16.59,43.65) v3(16.59,41.11) v3(16.59,32.85) v3(16.59,31.58) v3(16.59,8.72) v3(16.59,6.82) v3(16.59,4.91) v3(17.23,33.49) v3(17.23,32.22) v3(17.23,31.45) v3(17.23,16.98) v3(17.35,27.26) v3(17.35,26.63) v3(17.35,25.99) v3(17.35,15.83) v3(17.35,13.93) v3(17.35,11.64) v3(17.35,10.25) v3(17.61,30.31) v3(17.61,15.2) v3(17.68,10.85) v3(17.86,32.85) v3(17.86,31.58) v3(17.86,27.26) v3(17.86,11.39) v3(17.99,30.95) v3(17.99,13.93) v3(18.24,9.99) v3(18.5,33.49) v3(18.5,32.22) v3(18.5,31.45) v3(18.5,27.26) v3(18.75,9.36) v3(19,31.96) v3(19.13,67.14) v3(19.13,53.81) v3(19.13,51.27) v3(19.13,45.55) v3(19.13,35.39) v3(19.26,13.42) v3(19.39,8.72) v3(19.51,32.47) v3(19.77,12.91) v3(19.77,6.82) v3(20.15,8.72) v3(20.2,33.21) v3(20.31,28.03) v3(20.27,4.91) v3(20.78,28.41) v3(21.04,67.14) v3(21.04,65.24) v3(20.96,33.21) v3(21.04,12.53) v3(21.04,8.21) v3(21.49,45.78) v3(21.54,12.28) v3(21.67,43.65) v3(21.67,35.39) v3(21.72,33.21) v3(21.93,13.41) v3(21.93,8.09) v3(22.05,29.55) v3(22.43,28.03) v3(22.48,33.21) v3(22.69,13.41) v3(22.81,8.09) v3(22.94,6.82) v3(22.94,4.91) v3(23.27,33.23) v3(23.58,65.24) v3(23.58,63.33) v3(23.58,8.47) v3(23.86,32.37) v3(24.36,31.86) v3(24.59,8.34) v3(24.74,30.64) v3(24.85,36.66) v3(24.85,34.12) v3(24.85,9.61) v3(24.87,31.35) v3(24.97,29.93) v3(25.05,13.42) v3(24.97,11.13) v3(25.35,27.58) v3(25.48,8.72) v3(25.48,6.82) v3(25.48,1.74) v3(25.74,42.76) v3(25.74,40.03) v3(25.81,13.42) v3(25.86,38.63) v3(26.12,67.14) v3(26.12,65.24) v3(26.12,63.33) v3(26.12,61.43) v3(26.12,54.44) v3(26.12,37.42) v3(26.12,35.77) v3(26.12,33.99) v3(26.12,32.47) v3(26.12,30.69) v3(26.12,29.68) v3(26.88,59.78) v3(26.88,58.63) v3(27.84,31.23) v3(27.96,37.87) v3(28.15,59.78) v3(28.66,65.24) v3(28.66,63.33) v3(28.66,61.43) v3(28.66,10.63) v3(28.66,8.72) v3(28.66,6.82) v3(28.72,27.64) v3(28.78,31.2) v3(29.35,27.64) v3(29.54,13.54) v3(29.65,31.2) v3(29.93,59.78) v3(30.56,67.14) v3(30.56,65.24) v3(30.56,63.33) v3(30.56,61.43) v3(31.58,25.1) v3(31.57,16.08) v3(32.34,25.1) v3(32.47,31.58) v3(32.47,15.07) v3(32.47,12.53) v3(32.47,10.63) v3(32.47,8.72) v3(32.47,6.82) v3(33.1,65.24) v3(33.1,63.33) v3(33.1,61.43) v3(33.1,59.39) v3(34.69,39.01) v3(35.01,67.14) v3(35.01,65.24) v3(35.01,63.33) v3(35.01,61.43) v3(35.01,59.39) v3(35.01,56.35) v3(35.01,13.8) v3(35.01,10.63) v3(35.01,8.72) v3(35.01,6.82) v3(35.26,40.22) v3(35.64,37.93) v3(35.64,36.03) v3(35.64,34.12) v3(35.63,30.94) v3(35.63,29.92) v3(35.63,25.99) v3(35.63,24.84) v3(36.28,39.84) v3(36.78,30.94) v3(36.78,29.92) v3(36.78,25.99) v3(36.78,24.84) v3(37.55,65.24) v3(37.55,63.33) v3(37.55,61.43) v3(37.55,56.35) v3(37.55,53.81) v3(37.55,12.53) v3(37.67,9.36) v3(37.67,8.47) v3(37.67,7.58) v3(37.67,6.69) v3(37.67,5.8) v3(37.67,4.78) v3(38.18,52.54) v3(38.18,36.66) v3(38.18,34.12) v3(38.18,32.6) v3(38.69,7.58) v3(38.69,4.78) v3(38.82,13.8) v3(39.45,39.84) v3(39.45,38.57) v3(39.83,7.58) v3(39.83,4.78) v3(40.09,67.14) v3(40.09,65.24) v3(40.09,63.33) v3(40.09,61.43) v3(40.09,58.89) v3(40.09,56.35) v3(40.09,53.81) v3(40.09,52.54) v3(40.59,30.94) v3(40.59,29.92) v3(40.59,25.99) v3(40.59,24.84) v3(41.36,30.92) v3(41.38,29.9) v3(41.61,47.84) v3(41.61,13.67) v3(41.73,25.99) v3(41.73,24.84) v3(41.99,12.53) v3(42.63,65.24) v3(42.63,63.33) v3(42.63,61.43) v3(42.63,58.89) v3(42.63,56.35) v3(42.63,53.81) v3(42.63,52.54) v3(43.26,25.23) v3(43.87,24.82) v3(44.12,35.95) v3(44.12,30.84) v3(44.12,28.61) v3(44.15,10.88) v3(44.53,67.14) v3(44.53,65.24) v3(44.53,63.33) v3(44.53,61.43) v3(45.42,57.74) v3(46.44,63.33) v3(46.44,61.43) v3(46.44,58.89) v3(46.44,55.71) v3(46.44,6.82) v3(46.44,4.28) v3(47.71,56.35) v3(47.71,54.44) v3(48.09,36.66) v3(48.09,36.03) v3(48.09,35.39) v3(48.21,10.63) v3(48.34,67.14) v3(48.34,65.24) v3(48.34,63.33) v3(48.34,61.43) v3(48.85,36.66) v3(48.85,36.03) v3(48.85,35.39) v3(48.98,56.35) v3(49.61,54.44) v3(50.25,4.28) v3(50.37,34.5) v3(50.37,33.49) v3(50.88,65.24) v3(50.88,61.43) v3(51.01,34.5) v3(51.01,33.49) v3(51.52,56.35) v3(51.52,54.44) v3(51.52,52.54) v3(52.41,36.03) v3(52.41,34.5) v3(52.41,33.49) v3(52.79,56.47) v3(52.79,55.46) v3(52.91,53.93) v3(52.91,52.92) v3(53.04,33.49) v3(53.42,67.14) v3(53.42,65.24) v3(53.42,61.43) v3(53.42,56.47) v3(53.42,55.46) v3(53.55,53.93) v3(53.55,52.92) v3(53.68,36.03) v3(53.68,34.5) v3(53.68,33.49) v3(54.06,56.47) v3(54.06,55.46) v3(54.18,53.93) v3(54.18,52.92) v3(54.69,4.28) v3(55.07,36.66) v3(55.07,36.03) v3(55.07,9.48) v3(55.07,8.47) v3(55.07,6.94) v3(55.07,5.93) v3(55.2,34.5) v3(55.2,33.49) v3(55.33,10.75) v3(55.58,56.47) v3(55.58,55.46) v3(55.58,53.93) v3(55.58,52.92) v3(55.58,36.66) v3(55.58,36.03) v3(55.83,33.49) v3(55.83,9.48) v3(55.83,8.47) v3(55.83,6.94) v3(55.83,5.93) v3(56.09,36.03) v3(56.22,56.47) v3(56.22,55.46) v3(56.22,53.93) v3(56.22,52.92) v3(56.47,34.5) v3(56.47,33.49) v3(56.6,67.14) v3(56.6,65.24) v3(56.6,62.7) v3(56.6,61.43) v3(56.6,36.03) v3(56.85,56.47) v3(56.85,55.46) v3(56.85,53.93) v3(56.85,52.92) v3(56.85,9.61) v3(56.85,8.47) v3(56.85,6.94) v3(56.85,5.93) v3(57.87,4.28) v3(57.99,34.5) v3(57.99,33.49) v3(57.99,9.48) v3(57.99,8.47) v3(57.99,6.94) v3(57.99,5.93) v3(58.37,56.47) v3(58.37,55.46) v3(58.37,53.93) v3(58.37,52.92) v3(58.5,33.49) v3(59.01,56.47) v3(59.01,55.46) v3(59.01,53.93) v3(59.01,52.92) v3(59.01,33.49) v3(59.64,56.47) v3(59.64,55.46) v3(59.64,53.93) v3(59.64,52.92) v3(59.77,9.99) v3(59.77,7.45) v3(60.66,35.01) v3(60.66,34.25) v3(61.04,55.08) v3(61.17,53.93) v3(61.17,52.92) v3(61.17,35.01) v3(61.17,34.25) v3(61.17,33.61) v3(61.68,35.01) v3(61.68,34.25) v3(61.68,33.61) v3(61.68,32.98) v3(61.8,53.93) v3(61.8,52.92) v3(62.18,35.01) v3(62.18,34.25) v3(62.18,33.61) v3(62.18,32.98) v3(62.18,32.47) v3(62.31,55.08) v3(62.44,53.93) v3(62.44,52.92) v3(62.69,35.01) v3(62.69,34.25) v3(62.72,33.61) v3(63.71,55.08) v3(63.71,54.31) v3(63.71,53.55) v3(63.81,65.24) v3(63.81,64.22) v3(64.47,55.08) v3(64.47,54.31) v3(64.47,53.55) v3(64.47,52.79) v3(64.47,52.03) v3(64.6,25.61) v3(64.83,65.24) v3(64.83,64.22) v3(65.11,67.52) v3(65.75,32.59) v3(65.75,32.08) v3(65.75,31.57) v3(65.75,31.07) v3(66.38,25.87) v3(66.51,32.59) v3(66.51,32.08) v3(66.51,31.57) v3(66.51,31.07) v3(66.51,30.56) v3(67.14,25.87) v3(68.03,53.68) v3(68.03,53.17) v3(68.03,52.66) v3(68.03,52.16) v3(68.79,53.68) v3(68.79,53.17) v3(68.79,52.66) v3(68.79,52.16) v3(68.79,51.65) v3(69.55,40.6) v3(70.19,60.66) v3(70.19,60.16) v3(70.19,59.65) v3(70.19,58.25) v3(70.19,57.74) v3(70.19,57.24) v3(70.31,23.96) v3(70.57,41.11) v3(70.69,39.58) v3(70.69,39.07) v3(70.69,38.57) v3(70.69,37.17) v3(70.69,36.66) v3(70.69,36.15) v3(70.95,60.66) v3(70.95,60.16) v3(70.95,59.65) v3(70.95,58.25) v3(70.95,57.74) v3(70.95,57.24) v3(71.07,44.15) v3(71.07,42.63) v3(71.2,25.23) v3(71.2,22.06) v3(71.2,19.52) v3(71.46,39.58) v3(71.46,39.07) v3(71.46,38.57) v3(71.46,37.17) v3(71.46,36.66) v3(71.46,36.15) v3(72.22,32.98) v3(72.22,32.22) v3(72.47,25.23) v3(72.85,67.78) v3(73.11,44.92) v3(73.11,43.01) v3(73.74,22.06) v3(74.12,54.06) v3(74.12,53.3) v3(74.12,16.98) v3(75.01,51.27) v3(75.27,48.47) v3(75.65,53.81) v3(75.9,28.91) v3(75.9,27.9) v3(75.9,26.37) v3(75.9,25.61) v3(76.03,48.47) v3(76.28,22.06) v3(76.41,32.98) v3(76.41,32.22) v3(77.55,66.51) v3(77.55,63.97) v3(77.55,61.43) v3(77.55,58.89) v3(77.55,56.35) v3(77.55,53.81) v3(77.55,51.27) v3(77.55,48.09) v3(77.55,45.55) v3(77.55,32.22) v3(77.55,29.04) v3(77.55,25.87) v3(77.55,22.06) v4(1.34,58.63) v4(1.34,57.86) v4(1.34,57.1) v4(1.34,49.99) v4(1.34,49.23) v4(1.34,48.47) v4(1.34,45.42) v4(1.34,44.66) v4(1.34,43.89) v4(1.34,36.78) v4(1.34,36.02) v4(1.34,35.26) v4(1.34,32.34) v4(1.34,31.57) v4(1.34,30.81) v4(1.34,23.45) v4(1.34,22.68) v4(1.34,21.92) v4(1.34,19.26) v4(1.34,18.49) v4(1.34,17.73) v4(1.34,10.37) v4(1.34,9.6) v4(1.34,8.84) v4(1.98,58.63) v4(1.98,57.86) v4(1.98,57.1) v4(1.98,49.99) v4(1.98,49.23) v4(1.98,48.47) v4(1.98,45.42) v4(1.98,44.66) v4(1.98,43.89) v4(1.98,36.78) v4(1.98,36.02) v4(1.98,35.26) v4(1.98,32.34) v4(1.98,31.57) v4(1.98,30.81) v4(1.98,23.45) v4(1.98,22.68) v4(1.98,21.92) v4(1.98,19.26) v4(1.98,18.49) v4(1.98,17.73) v4(1.98,10.37) v4(1.98,9.6) v4(1.98,8.84) v4(3,58.63) v4(3,57.86) v4(3,57.1) v4(3,49.99) v4(3,49.23) v4(3,48.47) v4(3,45.42) v4(3,44.66) v4(3,43.89) v4(3,36.78) v4(3,36.02) v4(3,35.26) v4(3,32.34) v4(3,31.57) v4(3,30.81) v4(3,23.45) v4(3,22.68) v4(3,21.92) v4(3,19.26) v4(3,18.49) v4(3,17.73) v4(3,10.37) v4(3,9.6) v4(3,8.84) v4(4.01,58.63) v4(4.01,57.86) v4(4.01,57.1) v4(4.01,49.99) v4(4.01,49.23) v4(4.01,48.47) v4(4.01,45.42) v4(4.01,44.66) v4(4.01,43.89) v4(4.01,36.78) v4(4.01,36.02) v4(4.01,35.26) v4(4.01,32.34) v4(4.01,31.57) v4(4.01,30.81) v4(4.01,23.45) v4(4.01,22.68) v4(4.01,21.92) v4(4.01,19.26) v4(4.01,18.49) v4(4.01,17.73) v4(4.01,10.37) v4(4.01,9.6) v4(4.01,8.84) v4(4.77,58.63) v4(4.77,57.86) v4(4.77,57.1) v4(4.77,49.99) v4(4.77,49.23) v4(4.77,48.47) v4(4.77,45.42) v4(4.77,44.66) v4(4.77,43.89) v4(4.77,36.78) v4(4.77,36.02) v4(4.77,35.26) v4(4.77,32.34) v4(4.77,31.57) v4(4.77,30.81) v4(4.77,23.45) v4(4.77,22.68) v4(4.77,21.92) v4(4.77,19.26) v4(4.77,18.49) v4(4.77,17.73) v4(4.77,10.37) v4(4.77,9.6) v4(4.77,8.84) v4(10.24,8.98) v4(10.24,8.47) v4(10.24,7.96) v4(10.24,7.45) v4(10.75,8.98) v4(10.75,8.47) v4(10.75,7.45) v4(11.26,8.98) v4(11.26,8.47) v4(11.26,7.96) v4(11.26,7.45) v4(11.77,8.98) v4(11.77,8.47) v4(11.77,7.96) v4(11.77,7.45) v4(17.61,62.82) v4(17.61,62.32) v4(17.61,61.81) v4(17.61,61.3) v4(18.12,62.82) v4(18.12,62.32) v4(18.12,61.81) v4(18.12,61.3) v4(18.62,62.82) v4(18.62,62.32) v4(18.62,61.81) v4(18.62,61.3) v4(19.13,62.82) v4(19.13,62.32) v4(19.13,61.81) v4(19.13,61.3) v4(22.05,23.83) v4(22.05,23.33) v4(22.05,22.82) v4(22.05,22.31) v4(22.05,21.8) v4(22.05,21.29) v4(22.05,20.79) v4(22.05,20.28) v4(22.05,19.77) v4(22.05,19.26) v4(22.05,18.75) v4(22.05,18.25) v4(22.05,17.74) v4(22.05,17.23) v4(22.55,23.83) v4(22.56,23.33) v4(22.56,22.82) v4(22.56,22.31) v4(22.56,21.8) v4(22.56,21.29) v4(22.56,20.79) v4(22.56,20.28) v4(22.56,19.77) v4(22.56,19.26) v4(22.56,18.75) v4(22.56,18.25) v4(22.56,17.74) v4(22.56,17.23) v4(23.06,23.83) v4(23.07,23.33) v4(23.07,22.82) v4(23.07,22.31) v4(23.07,21.8) v4(23.07,21.29) v4(23.07,20.79) v4(23.07,20.28) v4(23.07,19.77) v4(23.07,19.26) v4(23.07,18.75) v4(23.07,18.25) v4(23.07,17.74) v4(23.07,17.23) v4(23.57,23.83) v4(23.58,23.33) v4(23.58,22.82) v4(23.58,22.31) v4(23.58,21.8) v4(23.58,21.29) v4(23.58,20.79) v4(23.58,20.28) v4(23.58,19.77) v4(23.58,19.26) v4(23.58,18.75) v4(23.58,18.25) v4(23.58,17.74) v4(23.58,17.23) v4(24.08,23.83) v4(24.08,23.33) v4(24.08,22.82) v4(24.08,22.31) v4(24.08,21.8) v4(24.08,21.29) v4(24.08,20.79) v4(24.08,20.28) v4(24.08,19.77) v4(24.08,19.26) v4(24.08,18.75) v4(24.08,18.25) v4(24.08,17.74) v4(24.08,17.23) v4(24.64,49.16) v4(24.59,23.83) v4(24.59,23.33) v4(24.59,22.82) v4(24.59,22.31) v4(24.59,21.8) v4(24.59,21.29) v4(24.59,20.79) v4(24.59,20.28) v4(24.59,19.77) v4(24.59,19.26) v4(24.59,18.75) v4(24.59,18.25) v4(24.59,17.74) v4(24.59,17.23) v4(25.09,23.83) v4(25.1,23.33) v4(25.1,22.82) v4(25.1,22.31) v4(25.1,21.8) v4(25.1,21.29) v4(25.1,20.79) v4(25.1,20.28) v4(25.1,19.77) v4(25.1,19.26) v4(25.1,18.75) v4(25.1,18.25) v4(25.1,17.74) v4(25.1,17.23) v4(25.6,23.83) v4(25.61,23.33) v4(25.61,22.82) v4(25.61,22.31) v4(25.61,21.8) v4(25.61,21.29) v4(25.61,20.79) v4(25.61,20.28) v4(25.61,19.77) v4(25.61,19.26) v4(25.61,18.75) v4(25.61,18.25) v4(25.61,17.74) v4(25.61,17.23) v4(26.11,23.83) v4(26.12,23.33) v4(26.12,22.82) v4(26.12,22.31) v4(26.12,21.8) v4(26.12,21.29) v4(26.12,20.79) v4(26.12,20.28) v4(26.12,19.77) v4(26.12,19.26) v4(26.12,18.75) v4(26.12,18.25) v4(26.12,17.74) v4(26.12,17.23) v4(26.62,23.83) v4(26.62,23.33) v4(26.62,22.82) v4(26.62,22.31) v4(26.62,21.8) v4(26.62,21.29) v4(26.62,20.79) v4(26.62,20.28) v4(26.62,19.77) v4(26.62,19.26) v4(26.62,18.75) v4(26.62,18.25) v4(26.62,17.74) v4(26.62,17.23) v4(27.13,23.83) v4(27.13,23.33) v4(27.13,22.82) v4(27.13,22.31) v4(27.13,21.8) v4(27.13,21.29) v4(27.13,20.79) v4(27.13,20.28) v4(27.13,19.77) v4(27.13,19.26) v4(27.13,18.75) v4(27.13,18.25) v4(27.13,17.74) v4(27.13,17.23) v4(27.63,23.83) v4(27.64,23.33) v4(27.64,22.82) v4(27.64,22.31) v4(27.64,21.8) v4(27.63,21.29) v4(27.64,20.79) v4(27.64,20.28) v4(27.63,19.76) v4(27.64,19.26) v4(27.64,18.75) v4(27.63,18.24) v4(27.64,17.74) v4(27.64,17.23) v4(28.15,23.83) v4(28.15,23.33) v4(28.15,22.82) v4(28.15,22.31) v4(28.15,21.8) v4(28.14,21.29) v4(28.15,20.79) v4(28.15,20.28) v4(28.14,19.76) v4(28.15,19.26) v4(28.15,18.75) v4(28.14,18.24) v4(28.15,17.74) v4(28.15,17.23) v4(28.66,23.83) v4(28.66,23.33) v4(28.66,22.82) v4(28.66,22.31) v4(28.66,21.8) v4(28.65,21.29) v4(28.66,20.79) v4(28.66,20.28) v4(28.65,19.76) v4(28.66,19.26) v4(28.66,18.75) v4(28.65,18.24) v4(28.66,17.74) v4(28.66,17.23) v4(28.66,1.74) v4(28.78,37.8) v4(28.78,37.3) v4(28.78,36.79) v4(28.78,36.28) v4(28.78,35.77) v4(28.78,35.26) v4(28.78,34.76) v4(28.78,34.25) v4(28.78,33.74) v4(28.78,33.23) v4(28.78,32.72) v4(28.78,32.22) v4(29.16,50.89) v4(29.16,50.38) v4(29.16,49.87) v4(29.16,49.36) v4(29.16,48.85) v4(29.16,48.35) v4(29.16,47.84) v4(29.16,47.33) v4(29.16,46.82) v4(29.16,46.31) v4(29.16,45.81) v4(29.16,45.3) v4(29.16,44.79) v4(29.29,37.8) v4(29.29,37.3) v4(29.29,36.79) v4(29.29,36.28) v4(29.29,35.77) v4(29.29,35.26) v4(29.29,34.76) v4(29.29,34.25) v4(29.29,33.74) v4(29.29,33.23) v4(29.29,32.72) v4(29.29,32.22) v4(29.67,50.89) v4(29.67,50.38) v4(29.67,49.87) v4(29.67,49.36) v4(29.67,48.85) v4(29.67,48.35) v4(29.67,47.84) v4(29.67,47.33) v4(29.67,46.82) v4(29.67,46.31) v4(29.67,45.81) v4(29.67,45.3) v4(29.67,44.79) v4(29.8,37.8) v4(29.8,37.3) v4(29.8,36.79) v4(29.8,36.28) v4(29.8,35.77) v4(29.8,35.26) v4(29.8,34.76) v4(29.8,34.25) v4(29.8,33.74) v4(29.8,33.23) v4(29.8,32.72) v4(29.8,32.22) v4(30.18,50.89) v4(30.18,50.38) v4(30.18,49.87) v4(30.18,49.36) v4(30.18,48.85) v4(30.18,48.35) v4(30.18,47.84) v4(30.18,47.33) v4(30.18,46.82) v4(30.18,46.31) v4(30.18,45.81) v4(30.18,45.3) v4(30.18,44.79) v4(30.31,37.8) v4(30.31,37.3) v4(30.31,36.79) v4(30.31,36.28) v4(30.31,35.77) v4(30.31,35.26) v4(30.31,34.76) v4(30.31,34.25) v4(30.31,33.74) v4(30.31,33.23) v4(30.31,32.72) v4(30.31,32.22) v4(30.69,50.89) v4(30.69,50.38) v4(30.69,49.87) v4(30.69,49.36) v4(30.69,48.85) v4(30.69,48.35) v4(30.69,47.84) v4(30.69,47.33) v4(30.69,46.82) v4(30.69,46.31) v4(30.69,45.81) v4(30.69,45.3) v4(30.69,44.79) v4(30.82,37.8) v4(30.82,37.3) v4(30.82,36.79) v4(30.82,36.28) v4(30.82,35.77) v4(30.82,35.26) v4(30.82,34.76) v4(30.82,34.25) v4(30.82,33.74) v4(30.82,33.23) v4(30.82,32.72) v4(30.82,32.22) v4(31.2,50.89) v4(31.2,50.38) v4(31.2,49.87) v4(31.2,49.36) v4(31.2,48.85) v4(31.2,48.35) v4(31.2,47.84) v4(31.2,47.33) v4(31.2,46.82) v4(31.2,46.31) v4(31.2,45.81) v4(31.2,45.3) v4(31.32,37.8) v4(31.32,37.3) v4(31.32,36.79) v4(31.32,36.28) v4(31.32,35.77) v4(31.32,35.26) v4(31.32,34.76) v4(31.32,34.25) v4(31.32,33.74) v4(31.32,33.23) v4(31.32,32.72) v4(31.32,32.22) v4(31.7,50.89) v4(31.7,50.38) v4(31.7,49.87) v4(31.7,49.36) v4(31.7,48.85) v4(31.7,48.35) v4(31.7,47.84) v4(31.7,47.33) v4(31.7,46.82) v4(31.7,46.31) v4(31.7,45.81) v4(31.83,37.8) v4(31.83,37.3) v4(31.83,36.79) v4(31.83,36.28) v4(31.83,35.77) v4(31.83,35.26) v4(31.83,34.76) v4(31.83,34.25) v4(31.83,33.74) v4(31.83,33.23) v4(31.83,32.72) v4(31.83,32.22) v4(32.21,50.89) v4(32.21,50.38) v4(32.21,49.87) v4(32.21,49.36) v4(32.21,48.85) v4(32.21,48.35) v4(32.21,47.84) v4(32.21,47.33) v4(32.21,46.82) v4(32.21,46.31) v4(32.34,37.8) v4(32.34,37.3) v4(32.34,36.79) v4(32.34,36.28) v4(32.34,35.77) v4(32.34,35.26) v4(32.34,34.76) v4(32.34,34.25) v4(32.34,33.74) v4(32.34,33.23) v4(32.34,32.72) v4(32.34,32.22) v4(32.47,1.74) v4(32.72,50.89) v4(32.72,50.38) v4(32.72,49.87) v4(32.72,49.36) v4(32.72,48.85) v4(32.72,48.35) v4(32.72,47.84) v4(32.72,47.33) v4(32.72,46.82) v4(32.72,44.79) v4(32.85,37.8) v4(32.85,37.3) v4(32.85,36.79) v4(32.85,36.28) v4(32.85,35.77) v4(32.85,35.26) v4(32.85,34.76) v4(32.85,34.25) v4(32.85,33.74) v4(32.85,33.23) v4(32.85,32.72) v4(32.85,32.22) v4(33.23,50.89) v4(33.23,50.38) v4(33.23,49.87) v4(33.23,49.36) v4(33.23,48.85) v4(33.23,48.35) v4(33.23,47.84) v4(33.23,47.33) v4(33.23,46.82) v4(33.23,45.3) v4(33.23,44.79) v4(33.36,37.8) v4(33.36,37.3) v4(33.36,36.79) v4(33.36,36.28) v4(33.36,35.77) v4(33.36,35.26) v4(33.36,34.76) v4(33.36,34.25) v4(33.36,33.74) v4(33.36,33.23) v4(33.36,32.72) v4(33.36,32.22) v4(33.74,50.89) v4(33.74,50.38) v4(33.74,49.87) v4(33.74,49.36) v4(33.74,48.85) v4(33.74,48.35) v4(33.74,47.84) v4(33.74,47.33) v4(33.74,46.82) v4(33.74,45.3) v4(33.74,44.79) v4(33.86,37.8) v4(33.86,37.3) v4(33.86,36.79) v4(33.86,36.28) v4(33.86,35.77) v4(33.86,35.26) v4(33.86,34.76) v4(33.86,34.25) v4(33.86,33.74) v4(33.86,33.23) v4(33.86,32.72) v4(33.86,32.22) v4(34.24,50.89) v4(34.24,50.38) v4(34.24,49.87) v4(34.24,49.36) v4(34.24,48.85) v4(34.24,48.35) v4(34.24,47.84) v4(34.24,47.33) v4(34.24,46.82) v4(34.24,45.3) v4(34.24,44.79) v4(34.37,37.8) v4(34.37,37.3) v4(34.37,36.79) v4(34.37,36.28) v4(34.37,35.77) v4(34.37,35.26) v4(34.37,34.76) v4(34.37,34.25) v4(34.37,33.74) v4(34.37,33.23) v4(34.37,32.72) v4(34.37,32.22) v4(34.75,50.89) v4(34.75,50.38) v4(34.75,49.87) v4(34.75,49.36) v4(34.75,48.85) v4(34.75,48.35) v4(34.75,47.84) v4(34.75,47.33) v4(34.75,46.82) v4(34.75,45.3) v4(34.75,44.79) v4(35.01,1.74) v4(35.26,50.89) v4(35.26,50.38) v4(35.26,49.87) v4(35.26,49.36) v4(35.26,48.85) v4(35.26,48.35) v4(35.26,47.84) v4(35.26,47.33) v4(35.26,46.82) v4(35.26,45.3) v4(35.77,15.71) v4(35.77,15.2) v4(35.77,14.69) v4(36.28,15.71) v4(36.28,15.2) v4(36.28,14.69) v4(36.78,15.71) v4(36.78,15.2) v4(36.78,14.69) v4(37.29,15.71) v4(37.29,15.2) v4(37.29,14.69) v4(45.29,1.74) v4(46.44,9.36) v4(48.09,6.94) v4(48.21,9.36) v4(48.21,8.09) v4(48.21,7.45) v4(50.25,1.74) v4(54.69,1.74) v4(59.64,21.8) v4(60.97,20.53) v4(64.85,6.82) v4(64.85,4.28) v4(64.85,1.74) v4(68.03,6.82) v4(68.03,1.74) v4(69.09,12.02) v4(69.09,11.31) v4(71.2,16.98) v4(71.2,14.44) v4(71.2,6.82) v4(71.2,4.28) v4(71.2,1.74) v4(71.58,9.74) v4(71.71,12.53) v4(73.74,6.82) v4(73.74,4.28) v4(73.74,1.74) v4(74.25,14.82) v4(74.25,11.9) v4(76.54,7.07) v4(76.54,5.04) v4(76.54,3.01) v4(77.3,1.74) v4(77.42,16.85) v4(77.42,14.18) v4(77.42,11.64)
